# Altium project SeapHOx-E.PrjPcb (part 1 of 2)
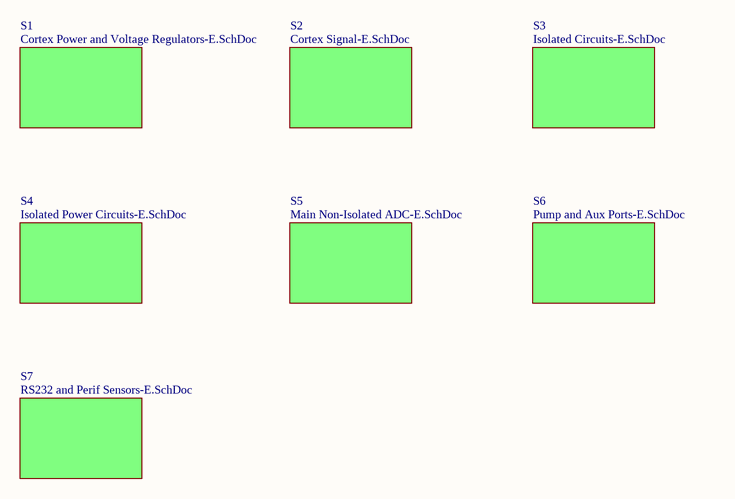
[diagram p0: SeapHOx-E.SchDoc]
8 sheets, 244 parts. Net scope: global (net labels, ports and power ports of the same name join across sheets).
Board file: SeapHOx-E.PcbDoc
Sheets:
  SeapHOx-E.SchDoc
    S1 = Cortex Power and Voltage Regulators-E.SchDoc
    S2 = Cortex Signal-E.SchDoc
    S3 = Isolated Circuits-E.SchDoc
    S7 = RS232 and Perif Sensors-E.SchDoc
    S4 = Isolated Power Circuits-E.SchDoc
    S5 = Main Non-Isolated ADC-E.SchDoc
    S6 = Pump and Aux Ports-E.SchDoc

## Sheet SeapHOx-E.SchDoc: SeapHOx ARM Controller
size Letter; PageSetup: Record=PageOptions¦CenterHorizontal=True¦CenterVertical=True¦PrintScale=0.94¦XCorrection=1.00¦YCorrection=1.00¦PrintKind=1¦BorderSize=5000000¦LeftOffset=0¦BottomOffset=0¦Orientation=2¦PaperLength=1000¦PaperWidth=1000¦Scale=100¦PaperSource=7¦PrintQuality=-4¦MediaType=1¦DitherType=10¦PaperKind=Letter¦PrintScaleMode=1

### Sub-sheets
S1 = Cortex Power and Voltage Regulators-E.SchDoc: no entries
S2 = Cortex Signal-E.SchDoc: no entries
S3 = Isolated Circuits-E.SchDoc: no entries
S4 = Isolated Power Circuits-E.SchDoc: no entries
S5 = Main Non-Isolated ADC-E.SchDoc: no entries
S6 = Pump and Aux Ports-E.SchDoc: no entries
S7 = RS232 and Perif Sensors-E.SchDoc: no entries

## Sheet Cortex Power and Voltage Regulators-E.SchDoc: SeapHOx ARM Controller
size Letter; DocumentNumber: 1; Revision: E; SheetNumber: 4; SheetTotal: 7; PageSetup: Record=PageOptions¦CenterHorizontal=True¦CenterVertical=True¦PrintScale=0.94¦XCorrection=1.00¦YCorrection=1.00¦PrintKind=0¦BorderSize=5000000¦LeftOffset=0¦BottomOffset=0¦Orientation=2¦PaperLength=1000¦PaperWidth=1000¦Scale=100¦PaperSource=7¦PrintQuality=-4¦MediaType=1¦DitherType=10¦PaperKind=Letter¦PrintScaleMode=1
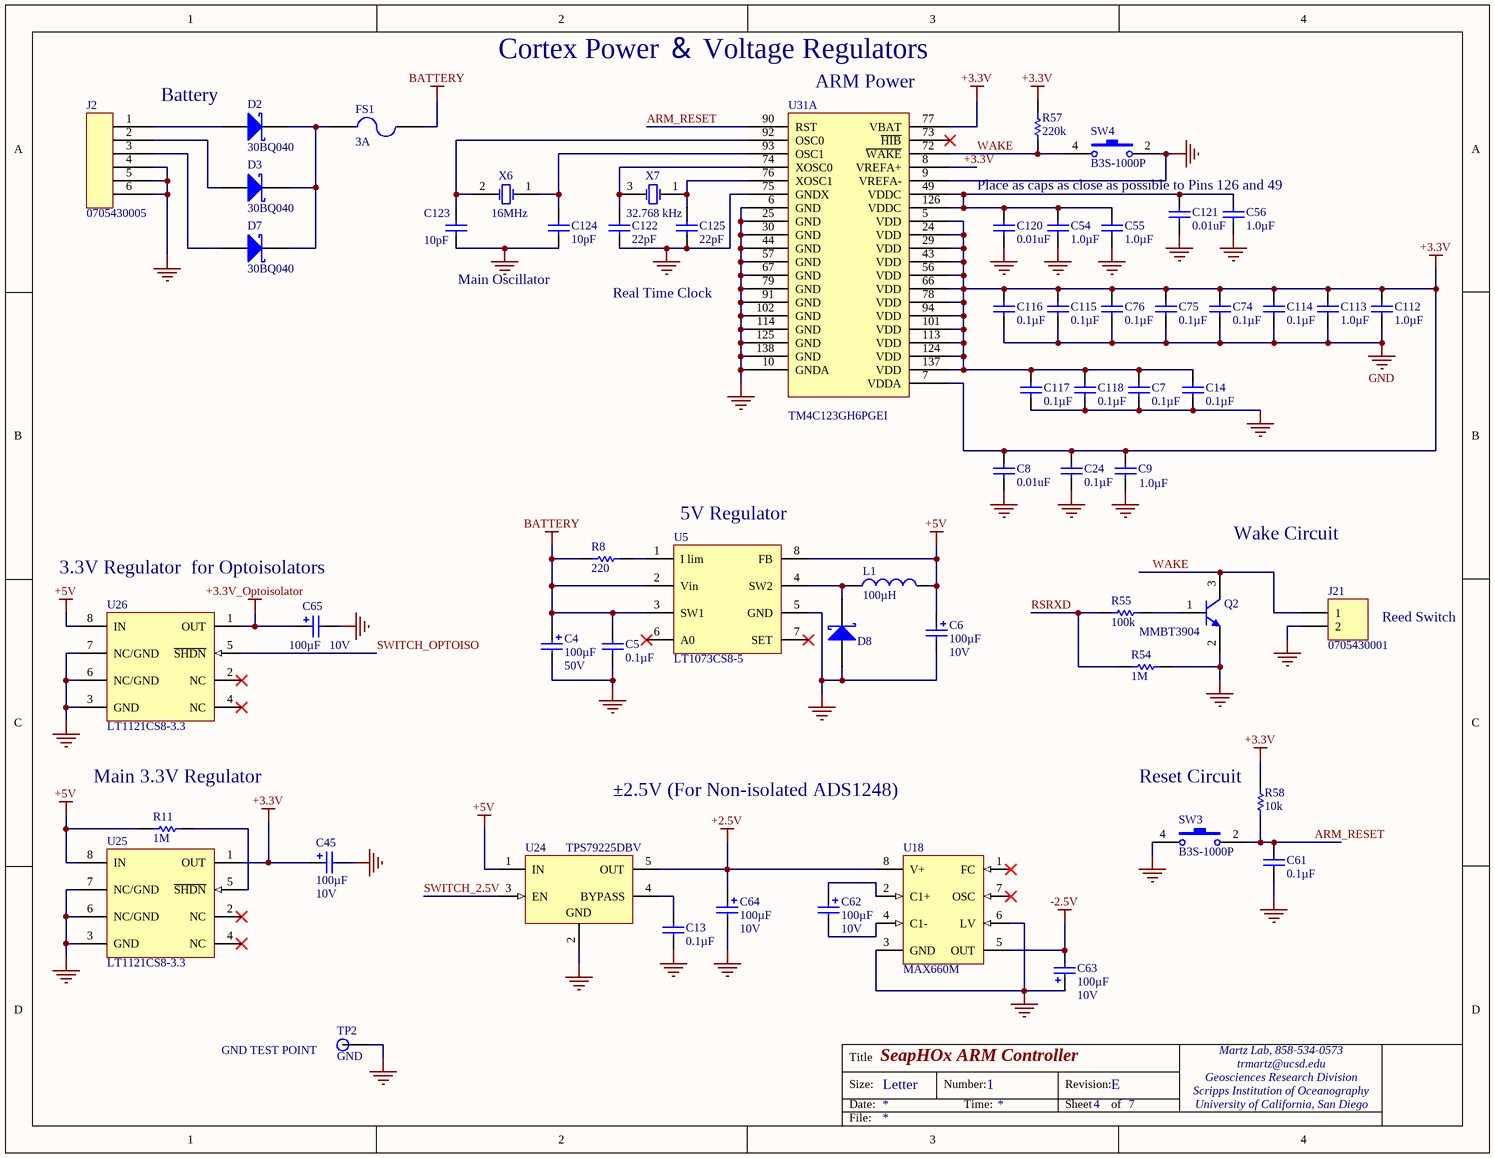
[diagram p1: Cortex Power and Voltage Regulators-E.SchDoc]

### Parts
C4  Capacitance: 100µF  Voltage Rating: 50V  [CAP-VS-HA]  (hidden comment: EEE-1HA101UP)
C5  Capacitance: 0.1µF  [CAPC0603(1608)100_M]  (hidden comment: 0.1uF/50V)
C6  Capacitance: 100µF  Voltage - Rated: 10V  [CAPMP7343X29N]  (hidden comment: T495D107K010ATE100)
C7  Capacitance: 0.1µF  [CAPC0603(1608)100_M]  (hidden comment: 0.1uF/50V)
C8  0.01uF  [CAPC0603(1608)100_M]
C9  Capacitance: 1.0µF  [CAPC0603(1608)100_M]
C13  Capacitance: 0.1µF  [CAPC0603(1608)100_M]  (hidden comment: 0.1uF/50V)
C14  Capacitance: 0.1µF  [CAPC0603(1608)100_M]  (hidden comment: 0.1uF/50V)
C24  Capacitance: 0.1µF  [CAPC0603(1608)100_M]  (hidden comment: 0.1uF/50V)
C45  Capacitance: 100µF  Voltage - Rated: 10V  [CAPMP7343X29N]  (hidden comment: T495D107K010ATE100)
C54  Capacitance: 1.0µF  [CAPC0603(1608)100_M]  (hidden comment: C1608X5R1H105K080AB)
C55  Capacitance: 1.0µF  [CAPC0603(1608)100_M]  (hidden comment: C1608X5R1H105K080AB)
C56  Capacitance: 1.0µF  [CAPC0603(1608)100_M]  (hidden comment: C1608X5R1H105K080AB)
C61  Capacitance: 0.1µF  [CAPC0603(1608)100_M]  (hidden comment: 0.1uF/50V)
C62  Capacitance: 100µF  Voltage - Rated: 10V  [CAPMP7343X29N]  (hidden comment: T495D107K010ATE100)
C63  Capacitance: 100µF  Voltage - Rated: 10V  [CAPMP7343X29N]  (hidden comment: T495D107K010ATE100)
C64  Capacitance: 100µF  Voltage - Rated: 10V  [CAPMP7343X29N]  (hidden comment: T495D107K010ATE100)
C65  Capacitance: 100µF  Voltage - Rated: 10V  [CAPMP7343X29N]  (hidden comment: T495D107K010ATE100)
C74  Capacitance: 0.1µF  [CAPC0603(1608)100_M]  (hidden comment: 0.1uF/50V)
C75  Capacitance: 0.1µF  [CAPC0603(1608)100_M]  (hidden comment: 0.1uF/50V)
C76  Capacitance: 0.1µF  [CAPC0603(1608)100_M]  (hidden comment: 0.1uF/50V)
C112  Capacitance: 1.0µF  [CAPC0603(1608)100_M]  (hidden comment: C1608X5R1H105K080AB)
C113  Capacitance: 1.0µF  [CAPC0603(1608)100_M]  (hidden comment: C1608X5R1H105K080AB)
C114  Capacitance: 0.1µF  [CAPC0603(1608)100_M]  (hidden comment: 0.1uF/50V)
C115  Capacitance: 0.1µF  [CAPC0603(1608)100_M]  (hidden comment: 0.1uF/50V)
C116  Capacitance: 0.1µF  [CAPC0603(1608)100_M]  (hidden comment: 0.1uF/50V)
C117  Capacitance: 0.1µF  [CAPC0603(1608)100_M]  (hidden comment: 0.1uF/50V)
C118  Capacitance: 0.1µF  [CAPC0603(1608)100_M]  (hidden comment: 0.1uF/50V)
C120  0.01uF  [CAPC0603(1608)100_M]
C121  0.01uF  [CAPC0603(1608)100_M]
C122  Capacitance: 22pF  [CAPC0603(1608)100_M]  (hidden comment: C1608C0G1H220J080AA)
C123  Capacitance: 10pF  [CAPC0603(1608)100_M]  (hidden comment: C1608C0G1H100D080AA)
C124  Capacitance: 10pF  [CAPC0603(1608)100_M]  (hidden comment: C1608C0G1H100D080AA)
C125  Capacitance: 22pF  [CAPC0603(1608)100_M]  (hidden comment: C1608C0G1H220J080AA)
D2  30BQ040  [DO-214AB]
D3  30BQ040  [DO-214AB]
D7  30BQ040  [DO-214AB]
D8  VS-10BQ100TRPBF  [DO-214AA]  (value not drawn)
FS1  Current Rating: 3A  [FUSE-NANO-SMD]  (hidden comment: 5A)
J2  0705430005  [70543-0005]
J21  0705430001  [70543-0001]
L1  Inductance: 100µH  [ELLATV]  (hidden comment: ELL-ATV101M)
Q2  MMBT3904  [SOT23-3]
R8  Resistance (Ohms): 220  [RESC0805(2012)_N]  (hidden comment: ERJ-6GEYJ221V)
R11  Resistance (Ohms): 1M  [RESC0805(2012)_N]  (hidden comment: ERJ-6GEYJ105V)
R54  Resistance (Ohms): 1M  [RESC0805(2012)_N]  (hidden comment: ERJ-6GEYJ105V)
R55  Resistance (Ohms): 100k  [RESC0805(2012)_N]  (hidden comment: ERJ-6GEYJ104V)
R57  Resistance (Ohms): 220k  [RESC0805(2012)_N]  (hidden comment: ERJ-6GEYJ224V)
R58  Resistance (Ohms): 10k  [RESC0805(2012)_N]  (hidden comment: ERJ-6GEYJ103V)
SW3  B3S-1000P  [B3S-100X]
SW4  B3S-1000P  [B3S-100X]
TP2  GND  [TEST-POINT-0.063]
U5  LT1073CS8-5  [SOIC8]
U18  MAX660M  [SOIC8]
U24  TPS79225DBV  [TI-DBV5]
U25  LT1121CS8-3.3  [SOIC8]
U26  LT1121CS8-3.3  [SOIC8]
U31  TM4C123GH6PGEI  [PGE144-M]  (part A of 3)
X6  Frequency: 16MHz  [ABM3]  (hidden comment: 16.000 MHz)
X7  32.768 kHz  [AB26TRB]

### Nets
+2.5V: C64.1 U18.8(V+) U24.5(OUT)
+3.3V: C7.1 C8.1 C9.1 C14.1 C24.1 C45.1 C74.2 C75.2 C76.2 C112.1 C113.1 C114.2 C115.1 C116.1 C117.1 C118.1 R57.1 R58.2 U25.1(OUT) U31.5(VDD) U31.7(VDDA) U31.8(VREFA+) U31.24(VDD) U31.29(VDD) U31.43(VDD) U31.56(VDD) U31.66(VDD) U31.77(VBAT) U31.78(VDD) U31.94(VDD) U31.101(VDD) U31.113(VDD) U31.124(VDD) U31.137(VDD)
+3.3V_Optoisolator: C65.1 U26.1(OUT)
+5V: C6.1 L1.2 R11.2 U5.8(FB) U24.1(IN) U25.8(IN) U26.8(IN)
-2.5V: C63.2 U18.5(OUT)
BATTERY: C4.1 C5.2 FS1.2 R8.1 U5.2(Vin) U5.3(SW1)
GND: C4.2 C5.1 C6.2 C7.2 C8.2 C9.2 C13.1 C14.2 C24.2 C45.2 C54.2 C55.2 C56.2 C61.1 C63.1 C64.2 C65.2 C74.1 C75.1 C76.1 C112.2 C113.2 C114.1 C115.2 C116.2 C117.2 C118.2 C120.2 C121.2 C122.2 C123.2 C124.2 C125.2 D8.1(A) J2.4 J2.5 J2.6 J21.2 Q2.2(E) R54.1 SW3.4 SW4.2 TP2.1(TP) U5.5(GND) U18.3(GND) U18.6(LV) U24.2(GND) U25.3(GND) U25.6(NC/GND) U25.7(NC/GND) U26.3(GND) U26.6(NC/GND) U26.7(NC/GND) U31.6(GND) U31.9(VREFA-) U31.10(GNDA) U31.25(GND) U31.30(GND) U31.44(GND) U31.57(GND) U31.67(GND) U31.75(GNDX) U31.79(GND) U31.91(GND) U31.102(GND) U31.114(GND) U31.125(GND) U31.138(GND)
ARM_RESET: C61.2 R58.1 SW3.2 U31.90(RST)
RSRXD: R54.2 R55.2
SWITCH_2.5V: U24.3(EN)
SWITCH_OPTOISO: U26.5(~{SHDN})
WAKE: J21.1 Q2.3(C) R57.2 SW4.4 U31.72(~{WAKE})
NetC13_2: C13.2 U24.4(BYPASS)
NetC54_1: C54.1 C55.1 C56.1 C120.1 C121.1 U31.49(VDDC) U31.126(VDDC)
NetC62_1: C62.1 U18.2(C1+)
NetC62_2: C62.2 U18.4(C1-)
NetC122_1: C122.1 U31.74(XOSC0) X7.3(OSC1)
NetC123_1: C123.1 U31.92(OSC0) X6.2(OSC1)
NetC124_1: C124.1 U31.93(OSC1) X6.1(OSC2)
NetC125_1: C125.1 U31.76(XOSC1) X7.1(OSC2)
NetD2_1: D2.1(A) J2.1
NetD2_2: D2.2(K) D3.2(K) D7.2(K) FS1.1
NetD3_1: D3.1(A) J2.2
NetD7_1: D7.1(A) J2.3
NetD8_2: D8.2(K) L1.1 U5.4(SW2)
NetQ2_1: Q2.1(B) R55.1
NetR8_2: R8.2 U5.1(I_lim)
NetR11_1: R11.1 U25.5(~{SHDN})

Not connected (* = marked no-connect by the designer): U5 6(A0)* 7(SET)*; U18 1(FC)* 7(OSC)*; U25 2(NC)* 4(NC)*; U26 2(NC)* 4(NC)*; U31 73(~{HIB})*

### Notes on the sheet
- (near D2) Battery
- Cortex Power ＆ Voltage Regulators
- (near U31) ARM Power
- Place as caps as close as possible to Pins 126 and 49
- Main Oscillator
- Real Time Clock
- (near U5) 5V Regulator
- Wake Circuit
- 3.3V Regulator  for Optoisolators
- Reed Switch
- Main 3.3V Regulator
- ±2.5V (For Non-isolated ADS1248)
- (near R58) Reset Circuit
- (near TP2) GND TEST POINT

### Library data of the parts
C4 = EEE-1HA101UP: CAP ALUM 100UF 50V 20% SMD; Manufacturer: Panasonic Electronic Components; Lifetime @ Temp.: 2000 Hrs @ 85°C; Ripple Current: 200mA; Surface Mount Land Size: 0.327" L x 0.327" W (8.30mm x 8.30mm)
C5 C7 C13 C14 C24 C61 C74-C76 C114-C118 = C0603C104K5RACTU: CAP CER 0.1UF 50V 10% X7R 0603; Manufacturer: Kemet
C6 C45 C62-C65 = T495D107K010ATE100: CAP TANT 100UF 10V 10% 2917; Manufacturer: Kemet; Manufacturer Size Code: D; ESR (Equivalent Series Resistance): 100 mOhm; Type: Molded; Lifetime @ Temp.: 2000 Hrs @ 85°C
C8 C120 C121 = C1608X7R1H103K080AA: CAP CER 10000PF 50V 10% X7R 0603; Manufacturer: TDK Corporation
C9 C54-C56 C112 C113 = C1608X5R1H105K080AB: CAP CER 1UF 50V 10% X5R 0603; Manufacturer: TDK Corporation
C122 C125 = C1608C0G1H220J080AA: CAP CER 22PF 50V 5% NP0 0603; Manufacturer: TDK Corporation; Temperature Coefficient: C0G, NP0
C123 C124 = C1608C0G1H100D080AA: CAP CER 10PF 50V NP0 0603; Manufacturer: TDK Corporation; Tolerance: ±0.5pF; Temperature Coefficient: C0G, NP0
D2 D3 D7 = VS-30BQ040TRPBF: DIODE SCHOTTKY 40V 3A SMC; Manufacturer: Vishay Semiconductor Diodes Division; Voltage - Forward (Vf) (Max) @ If: 530mV @ 3A; Speed: Fast Recovery =< 500ns, > 200mA (Io); Current - Reverse Leakage @ Vr: 500µA @ 40V; Thermal Resistance: 12°C/W Jl
D8 = VS-10BQ100TRPBF: DIODE SCHOTTKY 100V 1A DO214AA; Manufacturer: Vishay Semiconductor Diodes Division; Voltage - Forward (Vf) (Max) @ If: 780mV @ 1A; Speed: Fast Recovery =< 500ns, > 200mA (Io); Current - Reverse Leakage @ Vr: 500µA @ 100V; Thermal Resistance: 36°C/W Jl
FS1 = 0157003.DR: FUSE FAST 125VAC, 125VDC 3A SMD; Manufacturer: Littelfuse Inc; Fuse Type: Board Mount (Cartridge Style Excluded); Voltage Rating - AC: 125V; Breaking Capacity @ Rated Voltage: 50A; Melting I²t: 1.65; Approvals: cULus, PSE; DC Cold Resistance: 0.0229 Ohm
J2 = 0705430005: CONN HEADER 6POS .100 VERT GOLD; Manufacturer: Molex Inc; Connector Type: Header, Shrouded; Number of Positions: 6; Number of Positions Loaded: All; Pitch: 0.100" (2.54mm)
J21 = 0705430001: CONN HEADER 2POS .100 VERT GOLD; Manufacturer: Molex Inc; Connector Type: Header, Shrouded; Number of Positions: 2; Number of Positions Loaded: All; Pitch: 0.100" (2.54mm)
L1 = ELL-ATV101M: COIL PWR CHOKE 100UH 1A SMD; Manufacturer: Panasonic Electronic Components; Type: Wirewound; Material - Core: Ferrite; Tolerance: ±20%; Shielding: Shielded; DC Resistance (DCR): 180 mOhm; Frequency - Test: 100kHz
Q2 = MMBT3904: TRANSISTOR NPN GP 40V SOT23; Manufacturer: Micro Commercial Co; Manufacturer Part Number: MMBT3904-TP; Current - Collector (Ic) (Max): 200mA; Vce Saturation (Max) @ Ib, Ic: 300mV @ 5mA, 50mA; DC Current Gain (hFE) (Min) @ Ic, Vce: 100 @ 10mA, 1V; Power - Max: 350mW; Frequency - Transition: 300MHz
R8 = ERJ-6GEYJ221V: RES 220 OHM 1/8W 5% 0805 SMD; Manufacturer: Panasonic Electronic Components; Power (Watts): 0.125W, 1/8W; Temperature Coefficient: ±200ppm/°C
R11 R54 = ERJ-6GEYJ105V: RES 1M OHM 1/8W 5% 0805 SMD; Manufacturer: Panasonic Electronic Components; Power (Watts): 0.125W, 1/8W; Temperature Coefficient: ±200ppm/°C
R55 = ERJ-6GEYJ104V: RES 100K OHM 1/8W 5% 0805 SMD; Manufacturer: Panasonic Electronic Components; Power (Watts): 0.125W, 1/8W; Temperature Coefficient: ±200ppm/°C
R57 = ERJ-6GEYJ224V: RES 220K OHM 1/8W 5% 0805 SMD; Manufacturer: Panasonic Electronic Components; Power (Watts): 0.125W, 1/8W; Temperature Coefficient: ±200ppm/°C
R58 = ERJ-6GEYJ103V: RES 10K OHM 1/8W 5% 0805 SMD; Manufacturer: Panasonic Electronic Components; Power (Watts): 0.125W, 1/8W; Temperature Coefficient: ±200ppm/°C
SW3 SW4 = B3S-1000P: SWITCH TACTILE SPST-NO 0.05A 24V; Manufacturer: Omron Electronics Inc-EMC Div; Switch Function: Off-Mom; Contact Rating @ Voltage: 0.05A @ 24VDC; Actuator Type: Standard; Actuator Height off PCB, from Pins: 4.30mm; Actuator Orientation: Top Actuated; Outline: 6.60mm x 6.00mm; Illumination: Non-Illuminated; Operating Force: 160gf; Ingress Protection: IP67 - Dust Tight, Waterproof; Switch Travel: 0.25mm; Mechanical Life: 500,000 Cycles
TP2 = 5006: TEST POINT PC COMPACT .063"D BLK; Manufacturer: Keystone Electronics
U5 = LT1073CS8-5: IC REG BUCK BST INV 5V .4A 8SOIC; Manufacturer: Linear Technology; Manufacturer Part Number: LT1073CS8-5#PBF; Output Type: Fixed; Number of Outputs: 1; Voltage - Input: 1 V ~ 30 V; Frequency - Switching: 19kHz; Current - Output: 400mA; Synchronous Rectifier: No
U18 = MAX660M: IC REG MULTI CONFIG ADJ 8-SOIC; Manufacturer: Texas Instruments; Manufacturer Part Number: MAX660MX/NOPB; Output Type: Adjustable; Number of Outputs: 1; Voltage - Input: 1.5 V ~ 5.5 V; Frequency - Switching: 10kHz, 80kHz; Current - Output: 100mA; Synchronous Rectifier: No
U24 = TPS79225DBVT: IC REG LDO 2.5V 0.1A SOT23-5; Manufacturer: Texas Instruments; Number of Regulators: 1; Regulator Topology: Positive Fixed; Voltage - Input: 2.7 V ~ 5.5 V; Current - Output: 100mA (Max); Current - Limit (Min): 285mA
U25 U26 = LT1121CS8-3.3: IC REG LDO 3.3V 0.15A 8SOIC; Manufacturer: Linear Technology; Manufacturer Part Number: LT1121CS8-3.3#PBF; Number of Regulators: 1; Regulator Topology: Positive Fixed; Voltage - Input: 4.17 V ~ 30 V; Voltage - Dropout (Typical): 0.42V @ 150mA; Current - Output: 150mA
U31 = TM4C123GH6PGEI: IC MCU 32BIT 256KB FLASH 144LQFP; Manufacturer: Texas Instruments; Core Processor: ARM® Cortex™-M4F; Core Size: 32-Bit; Speed: 80MHz; Connectivity: CAN, I²C, IrDA, Microwire, QEI, SPI, SSI, UART/USART, USB OTG; Peripherals: Brown-out Detect/Reset, DMA, Motion PWM, POR, WDT; Number of I /O: 105; Program Memory Size: 256KB (256K x 8); EEPROM Size: 2K x 8; RAM Size: 32K x 8; Voltage - Supply (Vcc/Vdd): 1.08 V ~ 3.63 V; Data Converters: A/D 24x12b; Oscillator Type: Internal
X6 = ABM3-16.000MHZ-D2Y-T: CRYSTAL 16MHZ 18PF SMD; Manufacturer: Abracon Corporation; Frequency Stability: ±30ppm; Frequency Tolerance: ±20ppm; ESR (Equivalent Series Resistance): 40 Ohm; Operating Mode: Fundamental
X7 = AB26TRB-32.768KHZ-T: CRYSTAL 32.768KHZ 12.5PF THRU; Manufacturer: Abracon Corporation; Frequency Tolerance: ±20ppm; ESR (Equivalent Series Resistance): 50 kOhm; Operating Mode: Fundamental

## Sheet Cortex Signal-E.SchDoc: SeapHOx ARM Controller
size Letter; DocumentNumber: 1; Revision: E; SheetNumber: 3; SheetTotal: 7; PageSetup: Record=PageOptions¦CenterHorizontal=True¦CenterVertical=True¦PrintScale=0.94¦XCorrection=1.00¦YCorrection=1.00¦PrintKind=0¦BorderSize=5000000¦LeftOffset=0¦BottomOffset=0¦Orientation=2¦PaperLength=1000¦PaperWidth=1000¦Scale=100¦PaperSource=273¦PrintQuality=600¦MediaType=1¦DitherType=10¦PrintScaleMode=1¦PaperKind=Letter¦PaperIndex=1
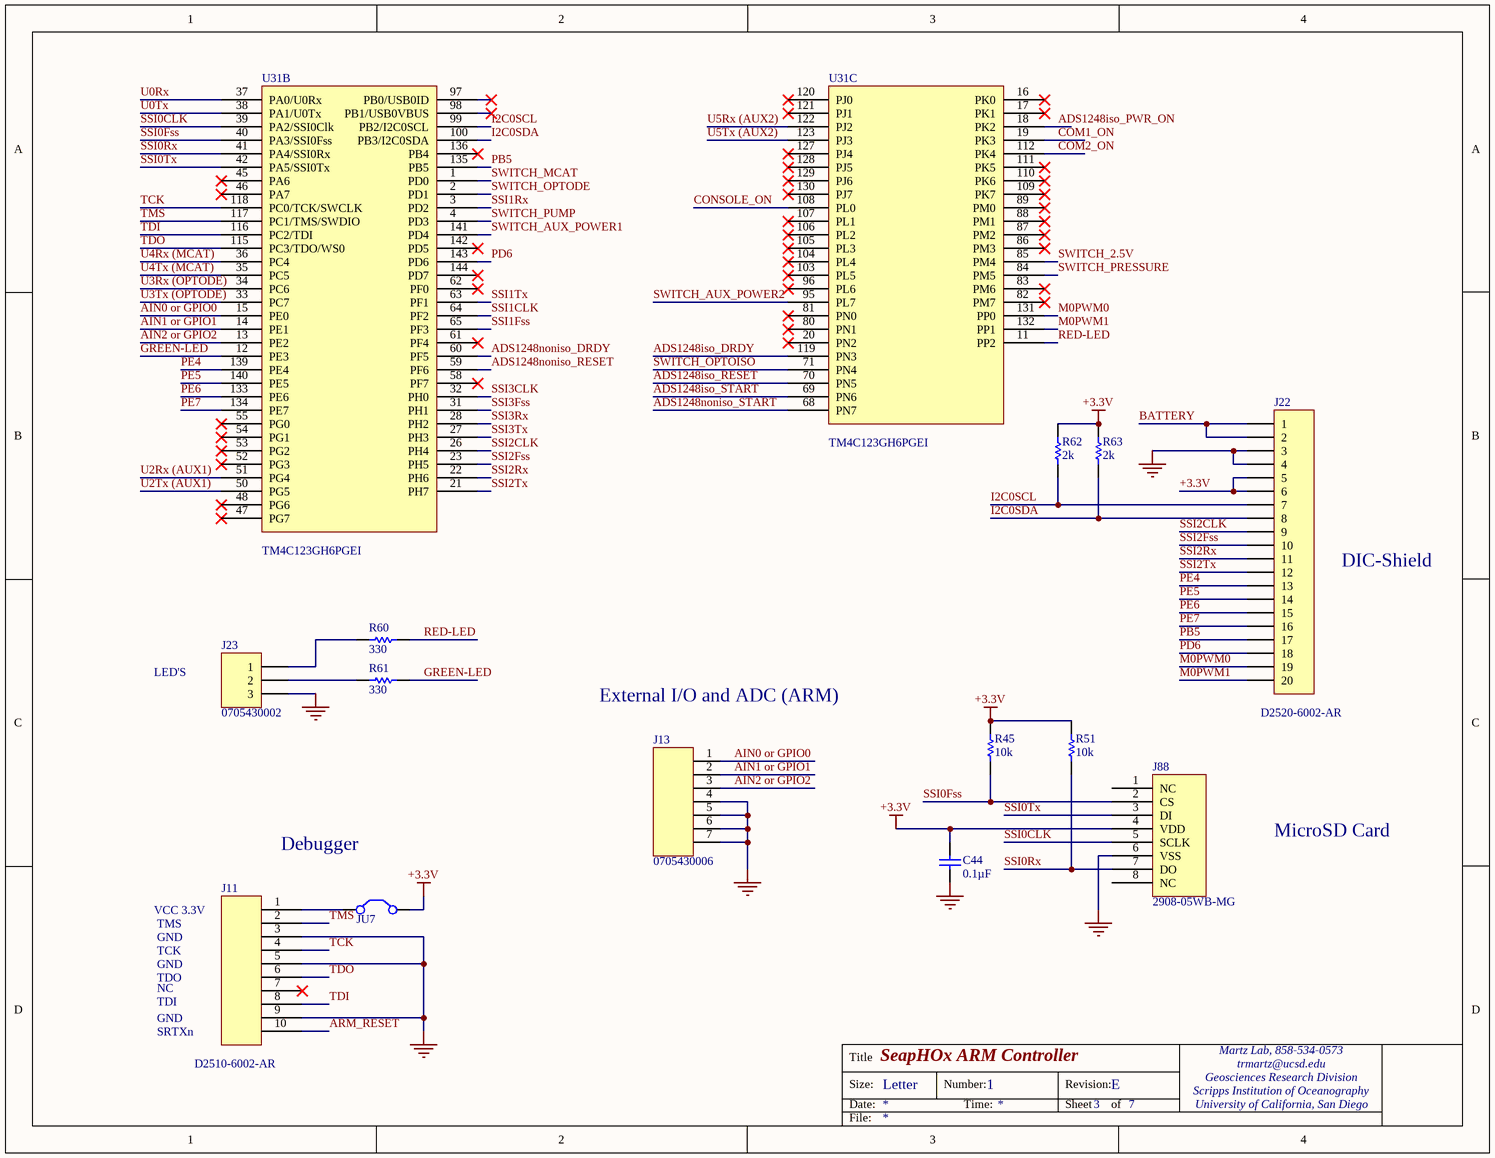
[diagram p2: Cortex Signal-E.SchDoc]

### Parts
C44  Capacitance: 0.1µF  [CAPC0603(1608)100_M]  (hidden comment: 0.1uF/50V)
J11  D2510-6002-AR  [D2510-6002]
J13  0705430006  [70543-0006]
J22  D2520-6002-AR  [D2520-6002]
J23  0705430002  [70543-0002]
J88  2908-05WB-MG  [2908-05]
JU7  68001-202HLF  [Jump-2 100mil]  (value not drawn)
R45  Resistance (Ohms): 10k  [RESC0805(2012)_N]  (hidden comment: ERJ-6GEYJ103V)
R51  Resistance (Ohms): 10k  [RESC0805(2012)_N]  (hidden comment: ERJ-6GEYJ103V)
R60  Resistance (Ohms): 330  [RESC0805(2012)_N]  (hidden comment: ERJ-6GEYJ331V)
R61  Resistance (Ohms): 330  [RESC0805(2012)_N]  (hidden comment: ERJ-6GEYJ331V)
R62  Resistance (Ohms): 2k  [RESC0805(2012)_N]  (hidden comment: ERJ-6GEYJ202V)
R63  Resistance (Ohms): 2k  [RESC0805(2012)_N]  (hidden comment: ERJ-6GEYJ202V)
U31  TM4C123GH6PGEI  [PGE144-M]  (parts B,C of 3)

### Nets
+3.3V: C44.2 J22.5 J22.6 J88.4(VDD) JU7.2(C2) R45.2 R51.2 R62.2 R63.2
BATTERY: J22.1 J22.2
GND: C44.1 J11.3 J11.5 J11.9 J13.4 J13.5 J13.6 J13.7 J22.3 J22.4 J23.3 J88.6(VSS)
ADS1248iso_DRDY: U31.119(PN3)
ADS1248iso_PWR_ON: U31.18(PK2)
ADS1248iso_RESET: U31.70(PN5)
ADS1248iso_START: U31.69(PN6)
ADS1248noniso_DRDY: U31.60(PF5)
ADS1248noniso_RESET: U31.59(PF6)
ADS1248noniso_START: U31.68(PN7)
AIN0 or GPIO0: J13.1 U31.15(PE0)
AIN1 or GPIO1: J13.2 U31.14(PE1)
AIN2 or GPIO2: J13.3 U31.13(PE2)
ARM_RESET: J11.10
COM1_ON: U31.19(PK3)
COM2_ON: U31.112(PK4)
CONSOLE_ON: U31.108(PL0)
GREEN-LED: R61.2 U31.12(PE3)
I2C0SCL: J22.7 R62.1 U31.99(PB2/I2C0SCL)
I2C0SDA: J22.8 R63.1 U31.100(PB3/I2C0SDA)
M0PWM0: J22.19 U31.131(PP0)
M0PWM1: J22.20 U31.132(PP1)
PB5: J22.17 U31.135(PB5)
PD6: J22.18 U31.143(PD6)
PE4: J22.13 U31.139(PE4)
PE5: J22.14 U31.140(PE5)
PE6: J22.15 U31.133(PE6)
PE7: J22.16 U31.134(PE7)
RED-LED: R60.2 U31.11(PP2)
SSI0CLK: J88.5(SCLK) U31.39(PA2/SSI0Clk)
SSI0Fss: J88.2(CS) R45.1 U31.40(PA3/SSI0Fss)
SSI0Rx: J88.7(DO) R51.1 U31.41(PA4/SSI0Rx)
SSI0Tx: J88.3(DI) U31.42(PA5/SSI0Tx)
SSI1CLK: U31.64(PF2)
SSI1Fss: U31.65(PF3)
SSI1Rx: U31.3(PD2)
SSI1Tx: U31.63(PF1)
SSI2CLK: J22.9 U31.26(PH4)
SSI2Fss: J22.10 U31.23(PH5)
SSI2Rx: J22.11 U31.22(PH6)
SSI2Tx: J22.12 U31.21(PH7)
SSI3CLK: U31.32(PH0)
SSI3Fss: U31.31(PH1)
SSI3Rx: U31.28(PH2)
SSI3Tx: U31.27(PH3)
SWITCH_2.5V: U31.85(PM4)
SWITCH_AUX_POWER1: U31.141(PD4)
SWITCH_AUX_POWER2: U31.95(PL7)
SWITCH_MCAT: U31.1(PD0)
SWITCH_OPTODE: U31.2(PD1)
SWITCH_OPTOISO: U31.71(PN4)
SWITCH_PRESSURE: U31.84(PM5)
SWITCH_PUMP: U31.4(PD3)
TCK: J11.4 U31.118(PC0/TCK/SWCLK)
TDI: J11.8 U31.116(PC2/TDI)
TDO: J11.6 U31.115(PC3/TDO/WS0)
TMS: J11.2 U31.117(PC1/TMS/SWDIO)
U0Rx: U31.37(PA0/U0Rx)
U0Tx: U31.38(PA1/U0Tx)
U2Rx (AUX1): U31.51(PG4)
U2Tx (AUX1): U31.50(PG5)
U3Rx (OPTODE): U31.34(PC6)
U3Tx (OPTODE): U31.33(PC7)
U4Rx (MCAT): U31.36(PC4)
U4Tx (MCAT): U31.35(PC5)
U5Rx (AUX2): U31.122(PJ2)
U5Tx (AUX2): U31.123(PJ3)
NetJ11_1: J11.1 JU7.1(C1)
NetJ23_1: J23.1 R60.1
NetJ23_2: J23.2 R61.1

Not connected (* = marked no-connect by the designer): J11 7*; J88 1(NC) 8(NC); U31 16(PK0)* 17(PK1)* 20(PN2)* 45(PA6)* 46(PA7)* 47(PG7)* 48(PG6)* 52(PG3)* 53(PG2)* 54(PG1)* 55(PG0)* 58(PF7)* 61(PF4)* 62(PF0)* 80(PN1)* 81(PN0)* 82(PM7)* 83(PM6)* 86(PM3)* 87(PM2)* 88(PM1)* 89(PM0)* 96(PL6)* 97(PB0/USB0ID)* 98(PB1/USB0VBUS)* 103(PL5)* 104(PL4)* 105(PL3)* 106(PL2)* 107(PL1)* 109(PK7)* 110(PK6)* 111(PK5)* 120(PJ0)* 121(PJ1)* 127(PJ4)* 128(PJ5)* 129(PJ6)* 130(PJ7)* 136(PB4)* 142(PD5)* 144(PD7)*

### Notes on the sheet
- DIC-Shield
- LED'S
- External I/O and ADC (ARM)
- MicroSD Card
- Debugger
- VCC 3.3V
- TMS
- GND
- TCK
- TDO
- NC
- TDI
- SRTXn

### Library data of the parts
C44 = C0603C104K5RACTU: as C5 on sheet Cortex Power and Voltage Regulators-E
J11 = D2510-6002-AR: CONN HEADER 10POS VERT 10GOLD; Manufacturer: 3M; Connector Type: Header, Shrouded; Number of Positions: 10; Number of Positions Loaded: All; Pitch: 0.100" (2.54mm)
J13 = 0705430006: CONN HEADER 7POS .100 VERT GOLD; Manufacturer: Molex Inc; Connector Type: Header, Shrouded; Number of Positions: 7; Number of Positions Loaded: All; Pitch: 0.100" (2.54mm)
J22 = D2520-6002-AR: CONN HEADER 20POS VERT 10GOLD; Manufacturer: 3M; Connector Type: Header, Shrouded; Number of Positions: 20; Number of Positions Loaded: All; Pitch: 0.100" (2.54mm)
J23 = 0705430002: CONN HEADER 3POS .100 VERT GOLD; Manufacturer: Molex Inc; Connector Type: Header, Shrouded; Number of Positions: 3; Number of Positions Loaded: All; Pitch: 0.100" (2.54mm)
J88 = 2908-05WB-MG: CONN EJECT MICROSD PUSH-PUSH SMD; Manufacturer: 3M; Card Type: Secure Digital - microSD™; Number of Positions: 10 (8 + 2); Connector Type: Connector and Ejector; Insertion, Removal Method: Push In, Push Out
JU7 = 68001-202HLF: BERGSTIK II .100" SR STRAIGHT; Manufacturer: FCI; Connector Type: Header, Unshrouded; Number of Positions: 2; Number of Positions Loaded: All; Pitch: 0.100" (2.54mm)
R45 R51 = ERJ-6GEYJ103V: as R58 on sheet Cortex Power and Voltage Regulators-E
R60 R61 = ERJ-6GEYJ331V: RES 330 OHM 1/8W 5% 0805 SMD; Manufacturer: Panasonic Electronic Components; Power (Watts): 0.125W, 1/8W; Temperature Coefficient: ±200ppm/°C
R62 R63 = ERJ-6GEYJ202V: RES 2K OHM 1/8W 5% 0805 SMD; Manufacturer: Panasonic Electronic Components; Power (Watts): 0.125W, 1/8W; Temperature Coefficient: ±200ppm/°C
U31 = TM4C123GH6PGEI: as U31 on sheet Cortex Power and Voltage Regulators-E

## Sheet Isolated Circuits-E.SchDoc: SeapHOx ARM Controller
size Letter; Organization: Martz Lab, 858-534-0573; Address1: trmartz@ucsd.edu; Address2: Geosciences Research; Address3: Division, Scripps Institution; Address4: of Oceanography, UCSD; DocumentNumber: 1; Revision: E; SheetNumber: 1; SheetTotal: 7
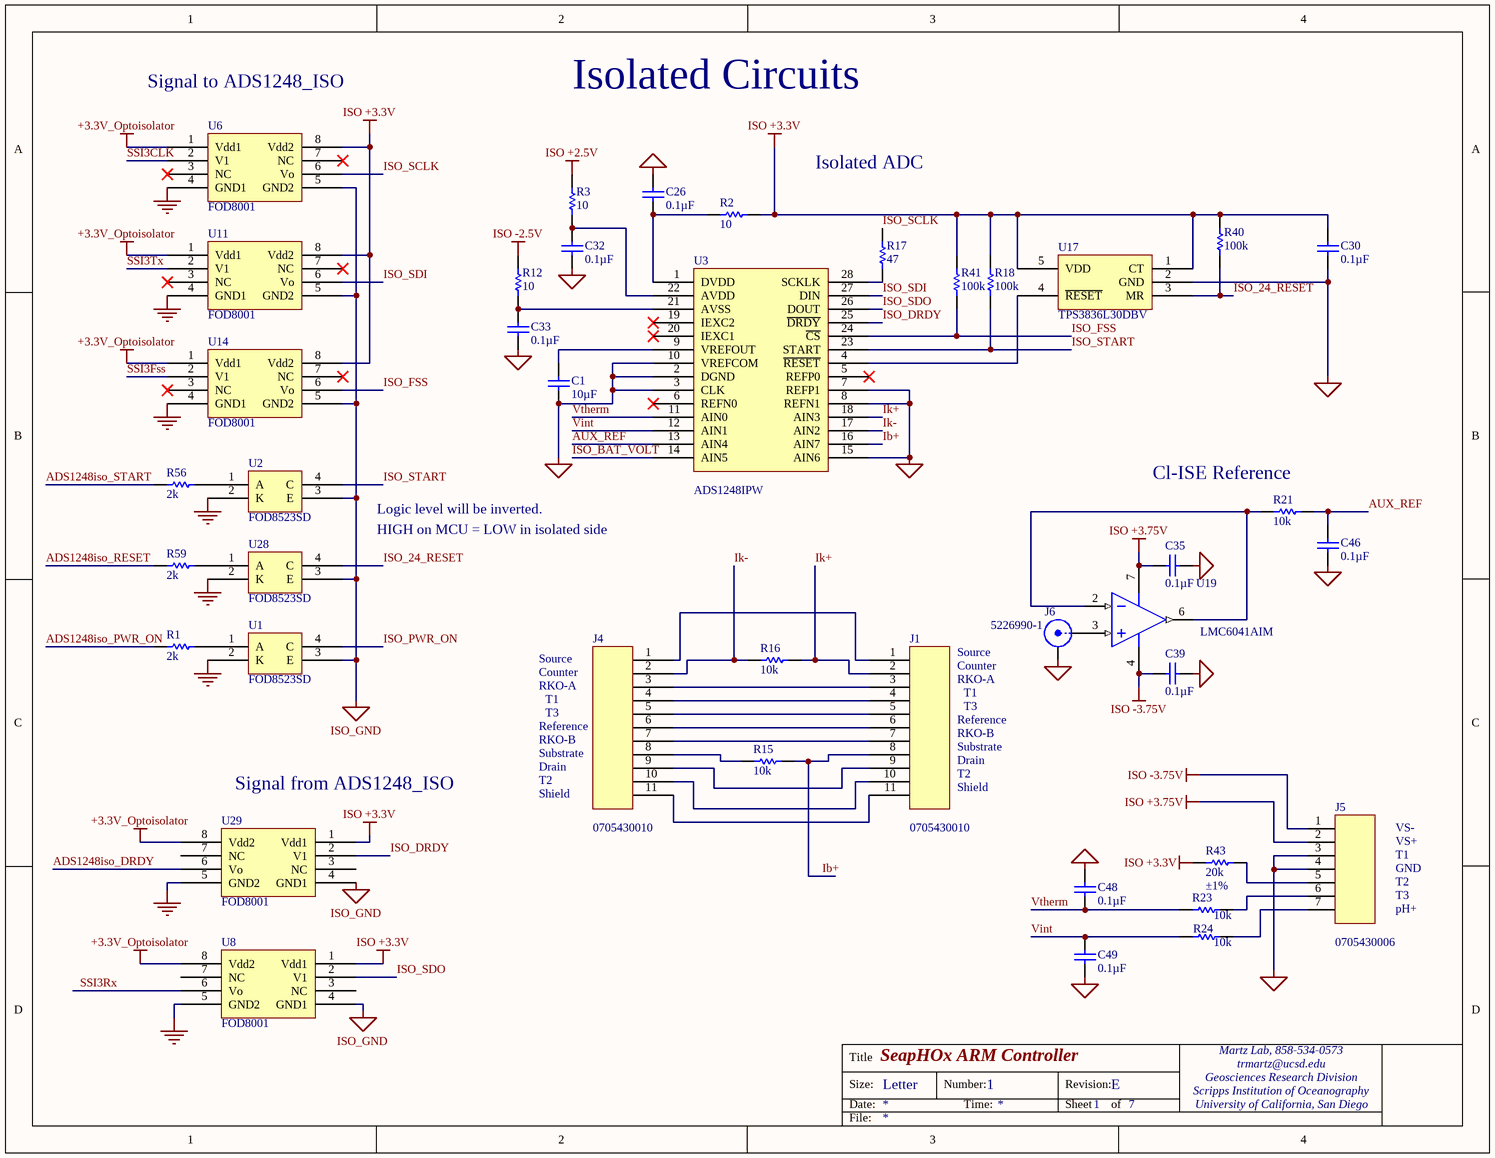
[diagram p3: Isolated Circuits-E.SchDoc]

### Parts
C1  Capacitance: 10µF  [CAPC0603(1608)100_M]  (hidden comment: C1608X5R1A106K080AC)
C26  Capacitance: 0.1µF  [CAPC0603(1608)100_M]  (hidden comment: 0.1uF/50V)
C30  Capacitance: 0.1µF  [CAPC0603(1608)100_M]  (hidden comment: 0.1uF/50V)
C32  Capacitance: 0.1µF  [CAPC0603(1608)100_M]  (hidden comment: 0.1uF/50V)
C33  Capacitance: 0.1µF  [CAPC0603(1608)100_M]  (hidden comment: 0.1uF/50V)
C35  Capacitance: 0.1µF  [CAPC0603(1608)100_M]  (hidden comment: 0.1uF/50V)
C39  Capacitance: 0.1µF  [CAPC0603(1608)100_M]  (hidden comment: 0.1uF/50V)
C46  Capacitance: 0.1µF  [CAPC0603(1608)100_M]  (hidden comment: 0.1uF/50V)
C48  Capacitance: 0.1µF  [CAPC0603(1608)100_M]  (hidden comment: 0.1uF/50V)
C49  Capacitance: 0.1µF  [CAPC0603(1608)100_M]  (hidden comment: 0.1uF/50V)
J1  0705430010  [70543-0010]
J4  0705430010  [70543-0010]
J5  0705430006  [70543-0006]
J6  5226990-1  [5226990-1]
R1  Resistance (Ohms): 2k  [RESC0805(2012)_N]  (hidden comment: ERJ-6GEYJ202V)
R2  Resistance (Ohms): 10  [RESC0805(2012)_N]  (hidden comment: ERJ-6GEYJ100V)
R3  Resistance (Ohms): 10  [RESC0805(2012)_N]  (hidden comment: ERJ-6GEYJ100V)
R12  Resistance (Ohms): 10  [RESC0805(2012)_N]  (hidden comment: ERJ-6GEYJ100V)
R15  Resistance (Ohms): 10k  [RESC0805(2012)_N]  (hidden comment: ERJ-6GEYJ103V)
R16  Resistance (Ohms): 10k  [RESC0805(2012)_N]  (hidden comment: ERJ-6GEYJ103V)
R17  Resistance (Ohms): 47  [RESC0603(1608)_N]  (hidden comment: ERJ-3GEYJ470V)
R18  Resistance (Ohms): 100k  [RESC0805(2012)_N]  (hidden comment: ERJ-6GEYJ104V)
R21  Resistance (Ohms): 10k  [RESC0805(2012)_N]  (hidden comment: ERJ-6GEYJ103V)
R23  Resistance (Ohms): 10k  [RESC0805(2012)_N]  (hidden comment: ERJ-6GEYJ103V)
R24  Resistance (Ohms): 10k  [RESC0805(2012)_N]  (hidden comment: ERJ-6GEYJ103V)
R40  Resistance (Ohms): 100k  [RESC0805(2012)_N]  (hidden comment: ERJ-6GEYJ104V)
R41  Resistance (Ohms): 100k  [RESC0805(2012)_N]  (hidden comment: ERJ-6GEYJ104V)
R43  Resistance (Ohms): 20k  Tolerance: ±1%  [RESC0805(2012)_N]  (hidden comment: ERJ-6ENF2002V)
R56  Resistance (Ohms): 2k  [RESC0805(2012)_N]  (hidden comment: ERJ-6GEYJ202V)
R59  Resistance (Ohms): 2k  [RESC0805(2012)_N]  (hidden comment: ERJ-6GEYJ202V)
U1  FOD8523SD  [4-SMD]
U2  FOD8523SD  [4-SMD]
U3  ADS1248  [TSSOP28]  (value not drawn)
U6  FOD8001  [MS-012-AA]
U8  FOD8001  [MS-012-AA]
U11  FOD8001  [MS-012-AA]
U14  FOD8001  [MS-012-AA]
U17  TPS3836L30DBV  [SOT23-5]
U19  LMC6041AIM  [MS-012-AA]
U28  FOD8523SD  [4-SMD]
U29  FOD8001  [MS-012-AA]

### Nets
+3.3V_Optoisolator: U6.1(Vdd1) U8.8(Vdd2) U11.1(Vdd1) U14.1(Vdd1) U29.8(Vdd2)
GND: U1.2(K) U2.2(K) U6.4(GND1) U8.5(GND2) U11.4(GND1) U14.4(GND1) U28.2(K) U29.5(GND2)
ISO +2.5V: R3.2
ISO +3.3V: C30.2 R2.2 R18.2 R40.2 R41.2 R43.1 U6.8(Vdd2) U8.1(Vdd1) U11.8(Vdd2) U14.8(Vdd2) U17.1(CT) U17.5(VDD) U29.1(Vdd1)
ISO +3.75V: C35.2 J5.2 U19.7(V+)
ISO -2.5V: R12.2
ISO -3.75V: C39.2 J5.1 U19.4(V-)
ISO_GND: C1.1 C26.2 C30.1 C32.1 C33.1 C35.1 C39.1 C46.1 C48.2 C49.1 J5.3 J5.4 J6.2(Y) U1.3(E) U2.3(E) U3.2(DGND) U3.3(CLK) U3.7(REFP1) U3.8(REFN1) U3.10(VREFCOM) U3.15(AIN6) U6.5(GND2) U8.4(GND1) U11.5(GND2) U14.5(GND2) U17.2(GND) U28.3(E) U29.4(GND1)
ADS1248iso_DRDY: U29.6(Vo)
ADS1248iso_PWR_ON: R1.1
ADS1248iso_RESET: R59.1
ADS1248iso_START: R56.1
AUX_REF: C46.2 R21.2 U3.13(AIN4)
Ib+: J1.8 R15.2 U3.16(AIN7)
Ik+: J1.2 R16.2 U3.18(AIN3)
Ik-: J4.2 R16.1 U3.17(AIN2)
ISO_24_RESET: R40.1 U17.3(MR) U28.4(C)
ISO_BAT_VOLT: U3.14(AIN5)
ISO_DRDY: U3.25(~{DRDY}) U29.2(V1)
ISO_FSS: R41.1 U3.24(~{CS}) U14.6(Vo)
ISO_PWR_ON: U1.4(C)
ISO_SCLK: R17.1 U6.6(Vo)
ISO_SDI: U3.27(DIN) U11.6(Vo)
ISO_SDO: U3.26(DOUT) U8.2(V1)
ISO_START: R18.1 U2.4(C) U3.23(START)
SSI3CLK: U6.2(V1)
SSI3Fss: U14.2(V1)
SSI3Rx: U8.6(Vo)
SSI3Tx: U11.2(V1)
Vint: C49.2 R24.1 U3.12(AIN1)
Vtherm: C48.1 R23.1 U3.11(AIN0)
NetC1_2: C1.2 U3.9(VREFOUT)
NetC26_1: C26.1 R2.1 U3.1(DVDD)
NetC32_2: C32.2 R3.1 U3.22(AVDD)
NetC33_2: C33.2 R12.1 U3.21(AVSS)
NetJ1_1: J1.1 J4.1
NetJ1_3: J1.3 J4.3
NetJ1_4: J1.4 J4.4
NetJ1_5: J1.5 J4.5
NetJ1_6: J1.6 J4.6
NetJ1_7: J1.7 J4.7
NetJ1_9: J1.9 J4.9
NetJ1_10: J1.10 J4.10
NetJ1_11: J1.11 J4.11
NetJ4_8: J4.8 R15.1
NetJ5_5: J5.5 R43.2
NetJ5_6: J5.6 R23.2
NetJ5_7: J5.7 R24.2
NetJ6_1: J6.1(X) U19.3(IN+)
NetR1_2: R1.2 U1.1(A)
NetR17_2: R17.2 U3.28(SCKLK)
NetR21_1: R21.1 U19.2(IN-) U19.6(OUT)
NetR56_2: R56.2 U2.1(A)
NetR59_2: R59.2 U28.1(A)
NetU3_4: U3.4(~{RESET}) U17.4(~{RESET})

Not connected (* = marked no-connect by the designer): U3 5(REFP0)* 6(REFN0)* 19(IEXC2)* 20(IEXC1)*; U6 3(NC)* 7(NC)*; U8 3(NC) 7(NC); U11 3(NC)* 7(NC)*; U14 3(NC)* 7(NC)*; U29 3(NC) 7(NC)

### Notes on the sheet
- Signal to ADS1248_ISO
- Isolated Circuits
- Isolated ADC
- (near R21) Cl-ISE Reference
- Logic level will be inverted.
- HIGH on MCU = LOW in isolated side
- Source
- (near J4) Counter
- RKO-A
- T1
- Counter
- (near J1) RKO-A
- (near J4) Reference
- RKO-B
- (near J4) Substrate
- Drain
- T3
- (near J1) Reference
- (near J1) RKO-B
- (near J1) Substrate
- (near J1) Drain
- (near J1) T2
- (near U29) Signal from ADS1248_ISO
- T2
- Shield
- (near J1) Shield
- VS-
- VS+
- GND
- pH+

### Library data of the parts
C1 = C1608X5R1A106K080AC: CAP CER 10UF 10V 10% X5R 0603; Manufacturer: TDK Corporation
C26 C30 C32 C33 C35 C39 C46 C48 C49 = C0603C104K5RACTU: as C5 on sheet Cortex Power and Voltage Regulators-E
J1 J4 = 0705430010: CONN HEADER 11POS .100 VERT GOLD; Manufacturer: Molex Inc; Connector Type: Header, Shrouded; Number of Positions: 11; Number of Positions Loaded: All; Pitch: 0.100" (2.54mm)
J5 = 0705430006: as J13 on sheet Cortex Signal-E
J6 = 5226990-1: CONN BNC JACK R/A 50 OHM PCB; Manufacturer: TE Connectivity; Connector Type: Jack, Female Socket; Contact Termination: Solder; Impedance: 50 Ohm; Frequency - Max: 4GHz; Body Material: Zinc; Body Finish: Nickel; Center Contact Material: Phosphor Bronze; Center Contact Plating: Tin; Dielectric Material: Polymethylpentene (PMP)
R1 R56 R59 = ERJ-6GEYJ202V: as R62 on sheet Cortex Signal-E
R2 R3 R12 = ERJ-6GEYJ100V: RES 10 OHM 1/8W 5% 0805 SMD; Manufacturer: Panasonic Electronic Components; Power (Watts): 0.125W, 1/8W; Temperature Coefficient: ±200ppm/°C
R15 R16 R21 R23 R24 = ERJ-6GEYJ103V: as R58 on sheet Cortex Power and Voltage Regulators-E
R17 = ERJ-3GEYJ470V: RES 47 OHM 1/10W 5% 0603 SMD; Manufacturer: Panasonic Electronic Components; Power (Watts): 0.1W, 1/10W; Temperature Coefficient: ±200ppm/°C
R18 R40 R41 = ERJ-6GEYJ104V: as R55 on sheet Cortex Power and Voltage Regulators-E
R43 = ERJ-6ENF2002V: RES 20K OHM 1/8W 1% 0805 SMD; Manufacturer: Panasonic Electronic Components; Power (Watts): 0.125W, 1/8W; Temperature Coefficient: ±100ppm/°C
U1 U2 U28 = FOD8523SD: OPTOCOUPLER DARL 5KVRMS 4SMD; Manufacturer: Fairchild Semiconductor; Number of Channels: 1; Input Type: DC; Voltage - Isolation: 5000Vrms; Current Transfer Ratio (Min): 1000% @ 1mA; Current Transfer Ratio (Max): 15000% @ 1mA; Voltage - Output: 300V; Current - Output / Channel: 150mA; Current - DC Forward (If): 50mA; Vce Saturation (Max): 1.2V; Output Type: Darlington
U3 = ADS1248IPW: IC ADC 24BIT DEL/SIG LN 28TSSOP; Manufacturer: Texas Instruments; Number of Bits: 24; Sampling Rate (Per Second): 2k; Data Interface: Serial, SPI™; Number of Converters: 1; Voltage Supply Source: Analog and Digital, Dual ±; Number of Inputs and Type: 7 Single-Ended, Unipolar; 7 Single-Ended, Bipolar; 4 Differential, Unipolar; 4 Differential, Bipolar
U6 U11 U14 = FOD8001: OPTOCOUPLER 3.3V 8-SOIC; Manufacturer: Fairchild Semiconductor; Voltage - Isolation: 3750Vrms; Number of Channels: 1, Unidirectional; Current - Output / Channel: 10mA; Data Rate: 25Mbps; Propagation Delay High - Low @ If: 25ns; Input Type: Logic; Output Type: Push-Pull, Totem Pole
U8 U29 = FOD8001: OPTOCOUPLER 3.3V 8-SOIC; Manufacturer: Fairchild Semiconductor; Voltage - Isolation: 3750Vrms; Number of Channels: 1, Unidirectional; Current - Output / Channel: 10mA; Input Type: Logic; Output Type: Push-Pull, Totem Pole; Data Rate: 25Mbps; Propagation Delay High - Low @ If: 25ns
U17 = TPS3836L30DBVT: IC 2.64V NANOPWR MON SOT-23-5; Manufacturer: Texas Instruments; Number of Voltages Monitored: 1; Output: Push-Pull, Totem Pole; Reset: Active Low; Reset Timeout: 100 ms Minimum
U19 = LMC6041AIM: IC OPAMP GP 75KHZ RRO 8SOIC; Manufacturer: Texas Instruments; Manufacturer Part Number: LMC6041AIM/NOPB; Amplifier Type: General Purpose; Number of Circuits: 1; Output Type: Rail-to-Rail; Slew Rate: 0.02 V/µs; Current - Input Bias: 0.002pA; Voltage - Input Offset: 1mV; Current - Supply: 18µA; Current - Output / Channel: 40mA; Voltage - Supply, Single/Dual (±): 4.5 V ~ 15.5 V, ±2.25 V ~ 7.75 V

## Sheet RS232 and Perif Sensors-E.SchDoc: SeapHOx ARM Controller
size Letter; DocumentNumber: 1; Revision: E; SheetNumber: 6; SheetTotal: 7
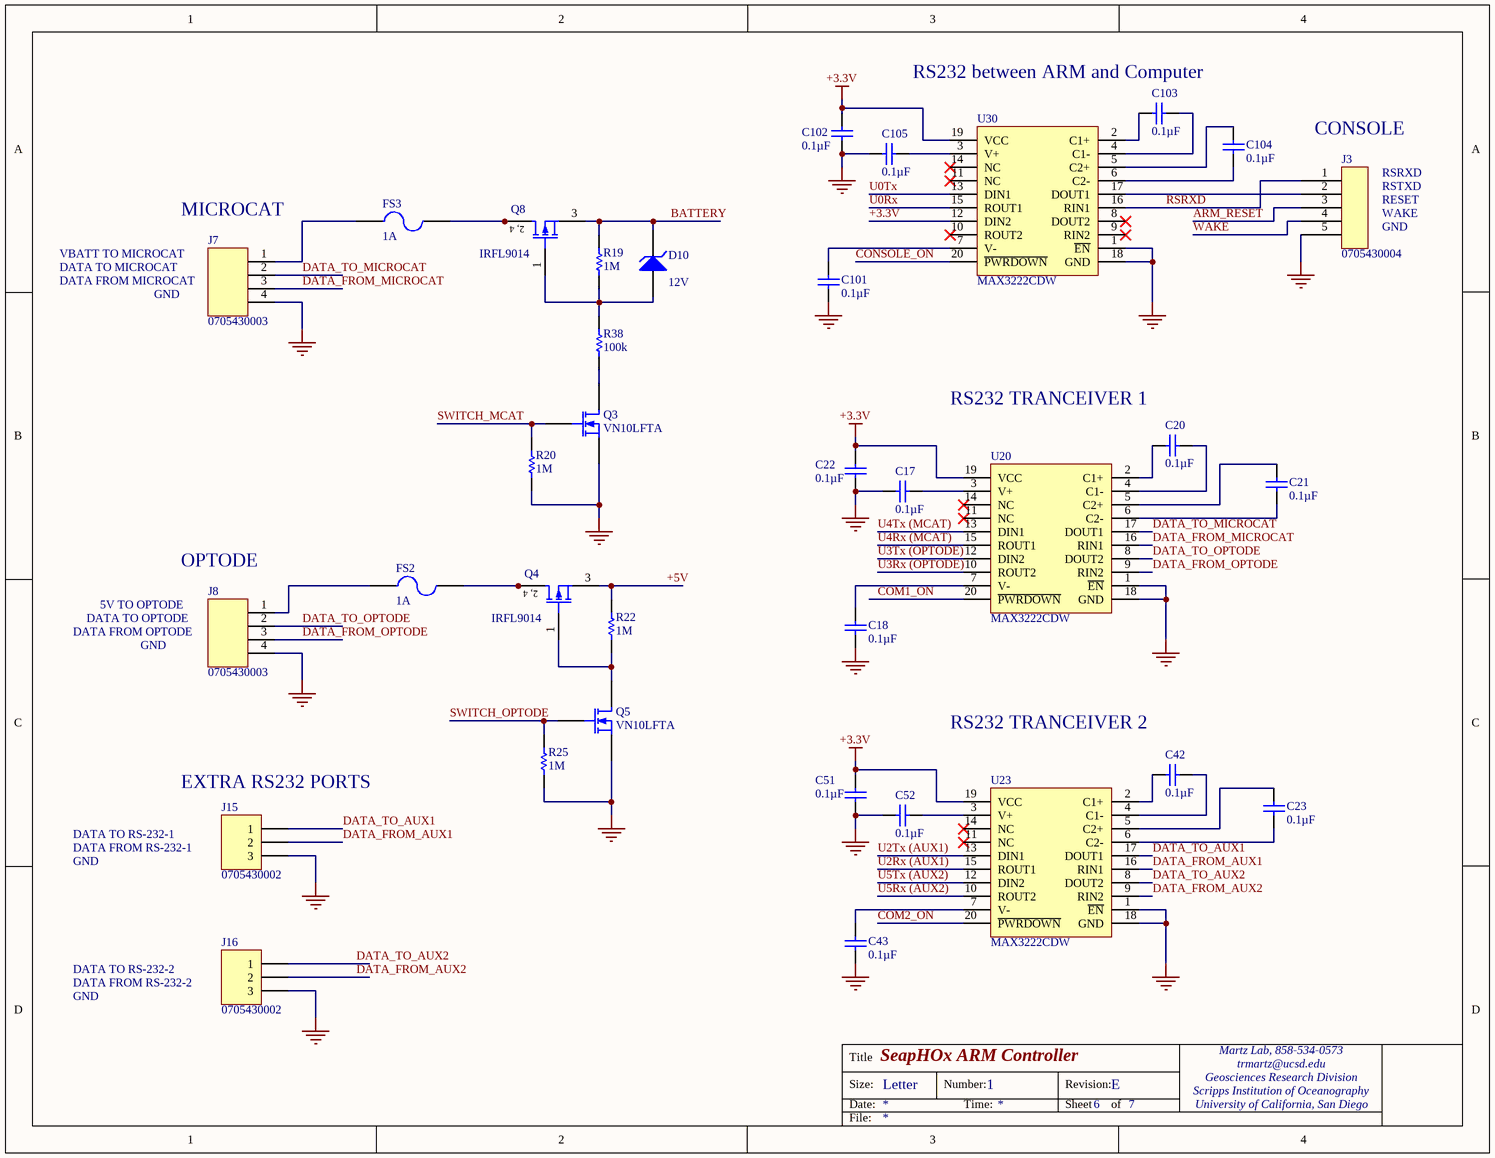
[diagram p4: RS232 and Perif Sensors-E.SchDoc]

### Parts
C17  Capacitance: 0.1µF  [CAPC0603(1608)100_M]  (hidden comment: 0.1uF/50V)
C18  Capacitance: 0.1µF  [CAPC0603(1608)100_M]  (hidden comment: 0.1uF/50V)
C20  Capacitance: 0.1µF  [CAPC0603(1608)100_M]  (hidden comment: 0.1uF/50V)
C21  Capacitance: 0.1µF  [CAPC0603(1608)100_M]  (hidden comment: 0.1uF/50V)
C22  Capacitance: 0.1µF  [CAPC0603(1608)100_M]  (hidden comment: 0.1uF/50V)
C23  Capacitance: 0.1µF  [CAPC0603(1608)100_M]  (hidden comment: 0.1uF/50V)
C42  Capacitance: 0.1µF  [CAPC0603(1608)100_M]  (hidden comment: 0.1uF/50V)
C43  Capacitance: 0.1µF  [CAPC0603(1608)100_M]  (hidden comment: 0.1uF/50V)
C51  Capacitance: 0.1µF  [CAPC0603(1608)100_M]  (hidden comment: 0.1uF/50V)
C52  Capacitance: 0.1µF  [CAPC0603(1608)100_M]  (hidden comment: 0.1uF/50V)
C101  Capacitance: 0.1µF  [CAPC0603(1608)100_M]  (hidden comment: 0.1uF/50V)
C102  Capacitance: 0.1µF  [CAPC0603(1608)100_M]  (hidden comment: 0.1uF/50V)
C103  Capacitance: 0.1µF  [CAPC0603(1608)100_M]  (hidden comment: 0.1uF/50V)
C104  Capacitance: 0.1µF  [CAPC0603(1608)100_M]  (hidden comment: 0.1uF/50V)
C105  Capacitance: 0.1µF  [CAPC0603(1608)100_M]  (hidden comment: 0.1uF/50V)
D10  Voltage - Zener (Nom) (Vz): 12V  [SOD323F 1005]
FS2  Current Rating: 1A  [FUSE-NANO-SMD]  (hidden comment: 5A)
FS3  Current Rating: 1A  [FUSE-NANO-SMD]  (hidden comment: 5A)
J3  0705430004  [70543-0004]
J7  0705430003  [70543-0003]
J8  0705430003  [70543-0003]
J15  0705430002  [70543-0002]
J16  0705430002  [70543-0002]
Q3  VN10LFTA  [SOT23-3]
Q4  IRFL9014  [SOT-223]
Q5  VN10LFTA  [SOT23-3]
Q8  IRFL9014  [SOT-223]
R19  Resistance (Ohms): 1M  [RESC0805(2012)_N]  (hidden comment: ERJ-6GEYJ105V)
R20  Resistance (Ohms): 1M  [RESC0805(2012)_N]  (hidden comment: ERJ-6GEYJ105V)
R22  Resistance (Ohms): 1M  [RESC0805(2012)_N]  (hidden comment: ERJ-6GEYJ105V)
R25  Resistance (Ohms): 1M  [RESC0805(2012)_N]  (hidden comment: ERJ-6GEYJ105V)
R38  Resistance (Ohms): 100k  [RESC0805(2012)_N]  (hidden comment: ERJ-6GEYJ104V)
U20  MAX3222CDW  [SOIC20]
U23  MAX3222CDW  [SOIC20]
U30  MAX3222CDW  [SOIC20]

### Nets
+3.3V: C22.1 C51.1 C102.1 U20.19(VCC) U23.19(VCC) U30.12(DIN2) U30.19(VCC)
+5V: Q4.3(S) R22.2
BATTERY: D10.2(K) Q8.3(S) R19.2
GND: C17.2 C18.2 C22.2 C43.2 C51.2 C52.2 C101.2 C102.2 C105.2 J3.5 J7.4 J8.4 J15.3 J16.3 Q3.2(S) Q5.2(S) R20.1 R25.1 U20.1(~{EN}) U20.18(GND) U23.1(~{EN}) U23.18(GND) U30.1(~{EN}) U30.18(GND)
ARM_RESET: J3.3
COM1_ON: U20.20(~{PWRDOWN})
COM2_ON: U23.20(~{PWRDOWN})
CONSOLE_ON: U30.20(~{PWRDOWN})
DATA_FROM_AUX1: J15.2 U23.16(RIN1)
DATA_FROM_AUX2: J16.2 U23.9(RIN2)
DATA_FROM_MICROCAT: J7.3 U20.16(RIN1)
DATA_FROM_OPTODE: J8.3 U20.9(RIN2)
DATA_TO_AUX1: J15.1 U23.17(DOUT1)
DATA_TO_AUX2: J16.1 U23.8(DOUT2)
DATA_TO_MICROCAT: J7.2 U20.17(DOUT1)
DATA_TO_OPTODE: J8.2 U20.8(DOUT2)
RSRXD: J3.1 U30.16(RIN1)
SWITCH_MCAT: Q3.1(G) R20.2
SWITCH_OPTODE: Q5.1(G) R25.2
U0Rx: U30.15(ROUT1)
U0Tx: U30.13(DIN1)
U2Rx (AUX1): U23.15(ROUT1)
U2Tx (AUX1): U23.13(DIN1)
U3Rx (OPTODE): U20.10(ROUT2)
U3Tx (OPTODE): U20.12(DIN2)
U4Rx (MCAT): U20.15(ROUT1)
U4Tx (MCAT): U20.13(DIN1)
U5Rx (AUX2): U23.10(ROUT2)
U5Tx (AUX2): U23.12(DIN2)
WAKE: J3.4
NetC17_1: C17.1 U20.3(V+)
NetC18_1: C18.1 U20.7(V-)
NetC20_1: C20.1 U20.2(C1+)
NetC20_2: C20.2 U20.4(C1-)
NetC21_1: C21.1 U20.5(C2+)
NetC21_2: C21.2 U20.6(C2-)
NetC23_1: C23.1 U23.5(C2+)
NetC23_2: C23.2 U23.6(C2-)
NetC42_1: C42.1 U23.2(C1+)
NetC42_2: C42.2 U23.4(C1-)
NetC43_1: C43.1 U23.7(V-)
NetC52_1: C52.1 U23.3(V+)
NetC101_1: C101.1 U30.7(V-)
NetC103_1: C103.1 U30.2(C1+)
NetC103_2: C103.2 U30.4(C1-)
NetC104_1: C104.1 U30.5(C2+)
NetC104_2: C104.2 U30.6(C2-)
NetC105_1: C105.1 U30.3(V+)
NetD10_1: D10.1(A) Q8.1(G) R19.1 R38.2
NetFS2_1: FS2.1 J8.1
NetFS2_2: FS2.2 Q4.2(D) Q4.4(D)
NetFS3_1: FS3.1 J7.1
NetFS3_2: FS3.2 Q8.2(D) Q8.4(D)
NetJ3_2: J3.2 U30.17(DOUT1)
NetQ3_3: Q3.3(D) R38.1
NetQ4_1: Q4.1(G) Q5.3(D) R22.1

Not connected (* = marked no-connect by the designer): U20 11(NC)* 14(NC)*; U23 11(NC)* 14(NC)*; U30 8(DOUT2)* 9(RIN2)* 10(ROUT2)* 11(NC)* 14(NC)*

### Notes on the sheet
- (near C103) RS232 between ARM and Computer
- (near J3) CONSOLE
- (near J7) MICROCAT
- (near J3) RSRXD
- (near J3) RSTXD
- (near J3) RESET
- (near J3) WAKE
- (near J3) GND
- DATA TO MICROCAT
- DATA FROM MICROCAT
- VBATT TO MICROCAT
- GND
- RS232 TRANCEIVER 1
- (near J8) OPTODE
- DATA FROM OPTODE
- DATA TO OPTODE
- 5V TO OPTODE
- RS232 TRANCEIVER 2
- DATA TO RS-232-1
- (near J15) EXTRA RS232 PORTS
- DATA FROM RS-232-1
- DATA TO RS-232-2
- DATA FROM RS-232-2

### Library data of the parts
C17 C18 C20-C23 C42 C43 C51 C52 C101-C105 = C0603C104K5RACTU: as C5 on sheet Cortex Power and Voltage Regulators-E
D10 = CZRF52C12: DIODE ZENER 12V 200MW 1005; Manufacturer: Comchip Technology; Voltage - Forward (Vf) (Max) @ If: 900mV @ 10mA; Current - Reverse Leakage @ Vr: 100nA @ 9V; Tolerance: ±5%; Impedance (Max) (Zzt): 20 Ohm
FS2 FS3 = 0157001.DR: FUSE FAST 125VAC, 125VDC 1A SMD; Manufacturer: Littelfuse Inc; Fuse Type: Board Mount (Cartridge Style Excluded); Voltage Rating - AC: 125V; Breaking Capacity @ Rated Voltage: 50A; Melting I²t: 0.459; Approvals: cULus, PSE; DC Cold Resistance: 0.1537 Ohm
J3 = 0705430004: CONN HEADER 5POS .100 VERT GOLD; Manufacturer: Molex Inc; Connector Type: Header, Shrouded; Number of Positions: 5; Number of Positions Loaded: All; Pitch: 0.100" (2.54mm)
J7 J8 = 0705430003: CONN HEADER 4POS .100 VERT GOLD; Manufacturer: Molex Inc; Connector Type: Header, Shrouded; Number of Positions: 4; Number of Positions Loaded: All; Pitch: 0.100" (2.54mm)
J15 J16 = 0705430002: as J23 on sheet Cortex Signal-E
Q3 Q5 = VN10LFTA: MOSFET N-CH 60V 150MA SOT23-3; Manufacturer: Diodes Inc; FET Type: MOSFET N-Channel, Metal Oxide; FET Feature: Standard; Current - Continuous Drain (Id) @ 25° C: 150mA (Ta); Rds On (Max) @ Id, Vgs: 5 Ohm @ 500mA, 10V; Vgs(th) (Max) @ Id: 2.5V @ 1mA; Input Capacitance (Ciss) @ Vds: 60pF @ 25V; Power - Max: 330mW
Q4 Q8 = IRFL9014TRPBF: MOSFET P-CH 60V 1.8A SOT223; Manufacturer: Vishay Siliconix; FET Type: MOSFET P-Channel, Metal Oxide; FET Feature: Standard; Current - Continuous Drain (Id) @ 25° C: 1.8A (Tc); Rds On (Max) @ Id, Vgs: 500 mOhm @ 1.1A, 10V; Vgs(th) (Max) @ Id: 4V @ 250µA; Gate Charge (Qg) @ Vgs: 12nC @ 10V; Input Capacitance (Ciss) @ Vds: 270pF @ 25V; Power - Max: 2W
R19 R20 R22 R25 = ERJ-6GEYJ105V: as R11 on sheet Cortex Power and Voltage Regulators-E
R38 = ERJ-6GEYJ104V: as R55 on sheet Cortex Power and Voltage Regulators-E
U20 U23 U30 = MAX3222CDW: IC DRVR/RCVR MULTCH RS232 20SOIC; Manufacturer: Texas Instruments; Number of Drivers/Receivers: 2/2; Duplex: Full; Receiver Hysteresis: 300mV; Data Rate: 250kbps; Voltage - Supply: 3 V ~ 5.5 V

## Sheet Isolated Power Circuits-E.SchDoc: SeapHOx ARM Controller
size Letter; DocumentNumber: 1; Revision: E; SheetNumber: 2; SheetTotal: 7; PageSetup: Record=PageOptions¦CenterHorizontal=True¦CenterVertical=True¦PrintScale=0.94¦XCorrection=1.00¦YCorrection=1.00¦PrintKind=0¦BorderSize=5000000¦LeftOffset=0¦BottomOffset=0¦Orientation=2¦PaperLength=1000¦PaperWidth=1000¦Scale=100¦PaperSource=7¦PrintQuality=-4¦MediaType=1¦DitherType=10¦PaperKind=Letter¦PrintScaleMode=1
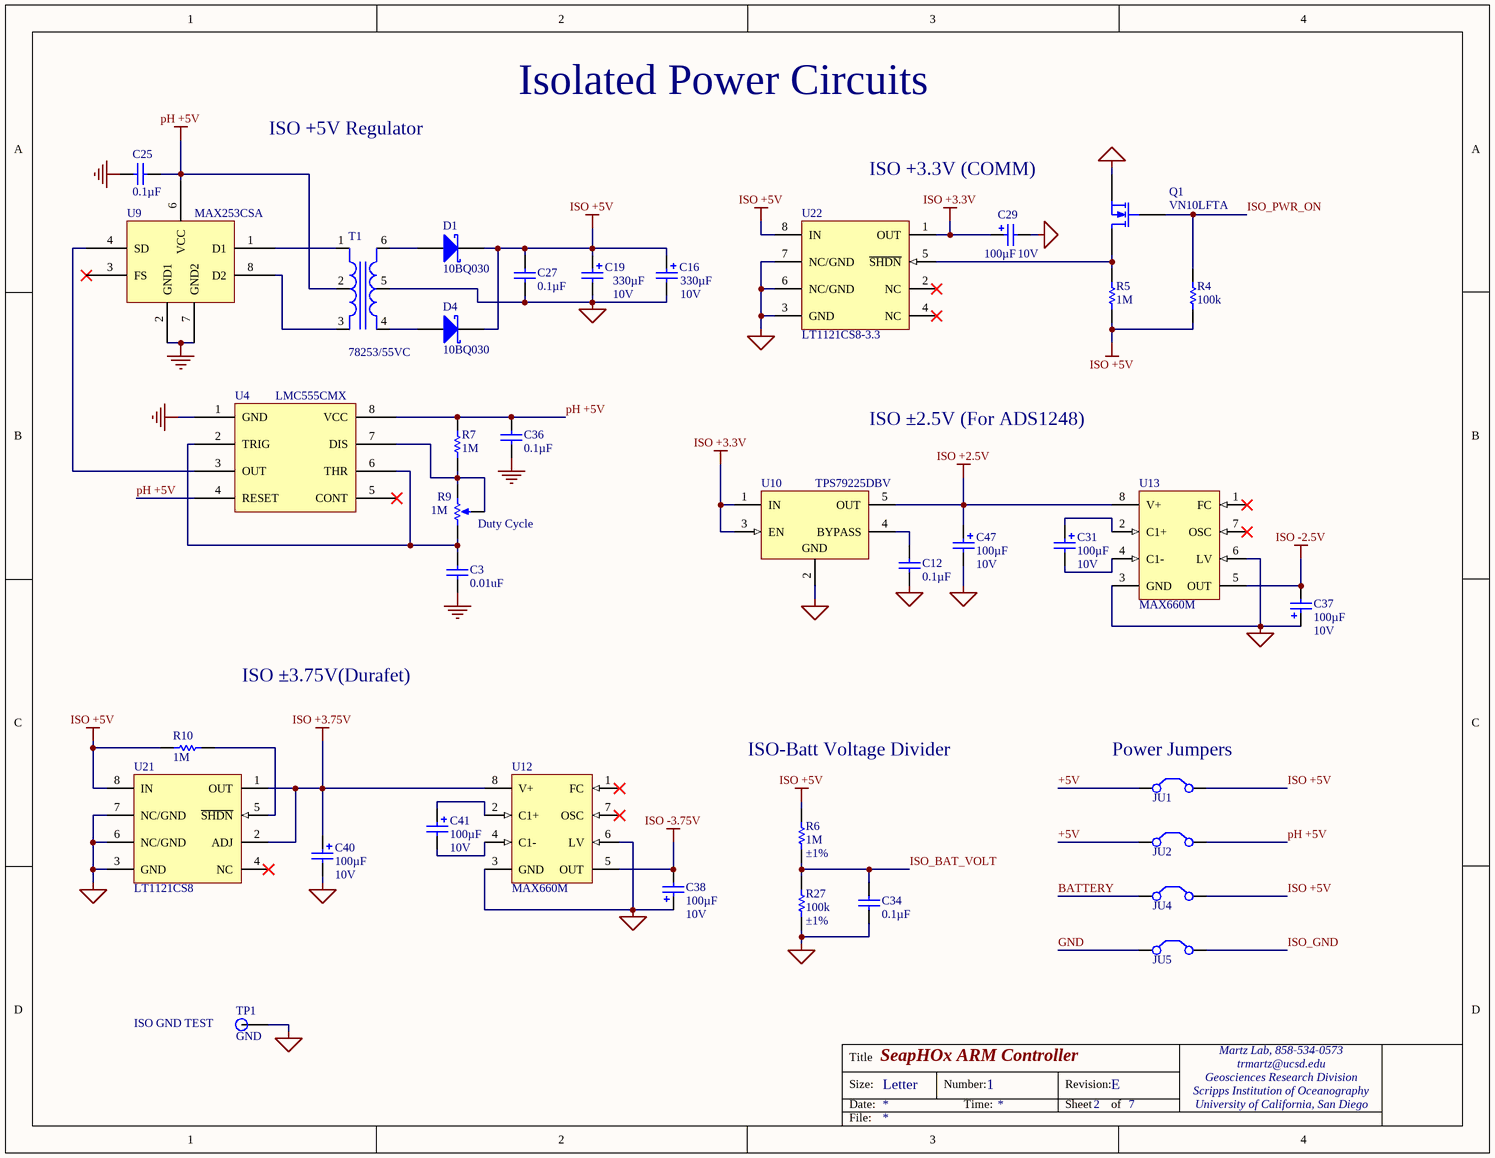
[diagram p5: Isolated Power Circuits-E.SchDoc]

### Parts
C3  0.01uF  [CAPC0603(1608)100_M]
C12  Capacitance: 0.1µF  [CAPC0603(1608)100_M]  (hidden comment: 0.1uF/50V)
C16  Voltage - Rated: 10V  Capacitance: 330µF  [CAPMP7343X29N]  (hidden comment: TR3D337M010C0100)
C19  Voltage - Rated: 10V  Capacitance: 330µF  [CAPMP7343X29N]  (hidden comment: TR3D337M010C0100)
C25  Capacitance: 0.1µF  [CAPC0603(1608)100_M]  (hidden comment: 0.1uF/50V)
C27  Capacitance: 0.1µF  [CAPC0603(1608)100_M]  (hidden comment: 0.1uF/50V)
C29  Capacitance: 100µF  Voltage - Rated: 10V  [CAPMP7343X29N]  (hidden comment: T495D107K010ATE100)
C31  Capacitance: 100µF  Voltage - Rated: 10V  [CAPMP7343X29N]  (hidden comment: T495D107K010ATE100)
C34  Capacitance: 0.1µF  [CAPC0603(1608)100_M]  (hidden comment: 0.1uF/50V)
C36  Capacitance: 0.1µF  [CAPC0603(1608)100_M]  (hidden comment: 0.1uF/50V)
C37  Capacitance: 100µF  Voltage - Rated: 10V  [CAPMP7343X29N]  (hidden comment: T495D107K010ATE100)
C38  Capacitance: 100µF  Voltage - Rated: 10V  [CAPMP7343X29N]  (hidden comment: T495D107K010ATE100)
C40  Capacitance: 100µF  Voltage - Rated: 10V  [CAPMP7343X29N]  (hidden comment: T495D107K010ATE100)
C41  Capacitance: 100µF  Voltage - Rated: 10V  [CAPMP7343X29N]  (hidden comment: T495D107K010ATE100)
C47  Capacitance: 100µF  Voltage - Rated: 10V  [CAPMP7343X29N]  (hidden comment: T495D107K010ATE100)
D1  10BQ030  [DO214AA]
D4  10BQ030  [DO214AA]
JU1  68001-202HLF  [Jump-2 100mil]  (value not drawn)
JU2  68001-202HLF  [Jump-2 100mil]  (value not drawn)
JU4  68001-202HLF  [Jump-2 100mil]  (value not drawn)
JU5  68001-202HLF  [Jump-2 100mil]  (value not drawn)
Q1  VN10LFTA  [SOT23-3]
R4  Resistance (Ohms): 100k  [RESC0805(2012)_N]  (hidden comment: ERJ-6GEYJ104V)
R5  Resistance (Ohms): 1M  [RESC0805(2012)_N]  (hidden comment: ERJ-6GEYJ105V)
R6  Resistance (Ohms): 1M  Tolerance: ±1%  [RESC0805(2012)_N]  (hidden comment: ERJ-6ENF1004V)
R7  Resistance (Ohms): 1M  [RESC0805(2012)_N]  (hidden comment: ERJ-6GEYJ105V)
R9  Resistance (Ohms): 1M  [3269W]  (hidden comment: 3269W-1-105GLF)
R10  Resistance (Ohms): 1M  [RESC0805(2012)_N]  (hidden comment: ERJ-6GEYJ105V)
R27  Resistance (Ohms): 100k  Tolerance: ±1%  [RESC0805(2012)_N]  (hidden comment: ERJ-6ENF1003V)
T1  78253/55VC  [DIP6]
TP1  GND  [TEST-POINT-0.063]
U4  LMC555CMX  [MS-012-AA]
U9  MAX253CSA  [SOIC8]
U10  TPS79225DBV  [TI-DBV5]
U12  MAX660M  [SOIC8]
U13  MAX660M  [SOIC8]
U21  LT1121CS8  [SOIC8]
U22  LT1121CS8-3.3  [SOIC8]

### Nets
+5V: JU1.1(C1) JU2.1(C1)
BATTERY: JU4.1(C1)
GND: C3.2 C25.2 C36.1 JU5.1(C1) U4.1(GND) U9.2(GND1) U9.7(GND2)
ISO +2.5V: C47.1 U10.5(OUT) U13.8(V+)
ISO +3.3V: C29.1 U10.1(IN) U10.3(EN) U22.1(OUT)
ISO +3.75V: C40.1 U12.8(V+) U21.1(OUT) U21.2(ADJ)
ISO +5V: C16.1 C19.1 C27.2 D1.2(K) D4.2(K) JU1.2(C2) JU4.2(C2) R4.1 R5.1 R6.2 R10.2 U21.8(IN) U22.8(IN)
ISO -2.5V: C37.2 U13.5(OUT)
ISO -3.75V: C38.2 U12.5(OUT)
ISO_GND: C12.1 C16.2 C19.2 C27.1 C29.2 C34.1 C37.1 C38.1 C40.2 C47.2 JU5.2(C2) Q1.2(S) R27.1 T1.5(SCT) TP1.1(TP) U10.2(GND) U12.3(GND) U12.6(LV) U13.3(GND) U13.6(LV) U21.3(GND) U21.6(NC/GND) U21.7(NC/GND) U22.3(GND) U22.6(NC/GND) U22.7(NC/GND)
pH +5V: C25.1 C36.2 JU2.2(C2) R7.2 T1.2(PCT) U4.4(RESET) U4.8(VCC) U9.6(VCC)
ISO_BAT_VOLT: C34.2 R6.1 R27.2
ISO_PWR_ON: Q1.1(G) R4.2
NetC3_1: C3.1 R9.3(CW) U4.2(TRIG) U4.6(THR)
NetC12_2: C12.2 U10.4(BYPASS)
NetC31_1: C31.1 U13.2(C1+)
NetC31_2: C31.2 U13.4(C1-)
NetC41_1: C41.1 U12.2(C1+)
NetC41_2: C41.2 U12.4(C1-)
NetD1_1: D1.1(A) T1.6(S1)
NetD4_1: D4.1(A) T1.4(S2)
NetQ1_3: Q1.3(D) R5.2 U22.5(~{SHDN})
NetR7_1: R7.1 R9.1(CCW) R9.2(W) U4.7(DIS)
NetR10_1: R10.1 U21.5(~{SHDN})
NetT1_1: T1.1(P1) U9.1(D1)
NetT1_3: T1.3(P2) U9.8(D2)
NetU4_3: U4.3(OUT) U9.4(SD)

Not connected (* = marked no-connect by the designer): U4 5(CONT)*; U9 3(FS)*; U12 1(FC)* 7(OSC)*; U13 1(FC)* 7(OSC)*; U21 4(NC)*; U22 2(NC)* 4(NC)*

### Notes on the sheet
- Isolated Power Circuits
- ISO +5V Regulator
- ISO +3.3V (COMM)
- ISO ±2.5V (For ADS1248)
- (near R9) Duty Cycle
- ISO ±3.75V(Durafet)
- ISO-Batt Voltage Divider
- (near JU1) Power Jumpers
- (near TP1) ISO GND TEST

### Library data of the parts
C3 = C1608X7R1H103K080AA: as C8 on sheet Cortex Power and Voltage Regulators-E
C12 C25 C27 C34 C36 = C0603C104K5RACTU: as C5 on sheet Cortex Power and Voltage Regulators-E
C16 C19 = TR3D337M010C0100: CAP TANT 330UF 10V 20% 2917; Manufacturer: Vishay Sprague; Manufacturer Size Code: D; ESR (Equivalent Series Resistance): 100 mOhm; Type: Molded
C29 C31 C37 C38 C40 C41 C47 = T495D107K010ATE100: as C6 on sheet Cortex Power and Voltage Regulators-E
D1 D4 = VS-10BQ030TRPBF: DIODE SCHOTTKY 30V 1A DO214AA; Manufacturer: Vishay Semiconductor Diodes Division; Voltage - Forward (Vf) (Max) @ If: 420mV @ 1A; Speed: Fast Recovery =< 500ns, > 200mA (Io); Current - Reverse Leakage @ Vr: 500µA @ 30V; Thermal Resistance: 25°C/W Jl
JU1 JU2 JU4 JU5 = 68001-202HLF: as JU7 on sheet Cortex Signal-E
Q1 = VN10LFTA: as Q3 on sheet RS232 and Perif Sensors-E
R4 = ERJ-6GEYJ104V: as R55 on sheet Cortex Power and Voltage Regulators-E
R5 R7 R10 = ERJ-6GEYJ105V: as R11 on sheet Cortex Power and Voltage Regulators-E
R6 = ERJ-6ENF1004V: RES 1M OHM 1/8W 1% 0805 SMD; Manufacturer: Panasonic Electronic Components; Power (Watts): 0.125W, 1/8W; Temperature Coefficient: ±100ppm/°C
R9 = 3269W-1-105GLF: TRIMMER 1M OHM 0.25W SMD; Manufacturer: Bourns Inc.; Power (Watts): 0.25W, 1/4W; Temperature Coefficient: ±100ppm/°C; Tolerance: ±10%; Number of Turns: 12; Adjustment Type: Top Adjustment; Resistive Material: Cermet
R27 = ERJ-6ENF1003V: RES 100K OHM 1/8W 1% 0805 SMD; Manufacturer: Panasonic Electronic Components; Power (Watts): 0.125W, 1/8W; Temperature Coefficient: ±100ppm/°C
T1 = 78253/55VC: XFRMR 5V IN/OUT MAX 253 DIP; Manufacturer: Murata Power Solutions Inc; Inductance: 240µH; For Use With/Related Products: MAX253
TP1 = 5006: as TP2 on sheet Cortex Power and Voltage Regulators-E
U4 = LMC555CMX: IC OSC MONO TIMING 3MHZ 8-SOIC; Manufacturer: Texas Instruments; Voltage - Supply: 1.5 V ~ 15 V; Current - Supply: 150µA
U9 = MAX253CSA: Gate Drivers Transformer Driver for Iso RS-485 Int; Manufacturer: Maxim Integrated; Manufacturer Part Number: MAX253CSA+; Output Current: 1 A; Supply Current: 0.45 mA; Maximum Power Dissipation: 471 mW; Number of Drivers: 1; Operating Supply Voltage: 3.3 V, 5 V; Supply Voltage - Max: 6 V; Supply Voltage - Min: 2.5 V
U10 = TPS79225DBVT: as U24 on sheet Cortex Power and Voltage Regulators-E
U12 U13 = MAX660M: as U18 on sheet Cortex Power and Voltage Regulators-E
U21 = LT1121CS8: IC REG LDO ADJ 0.15A 8SOIC; Manufacturer: Linear Technology; Manufacturer Part Number: LT1121CS8#PBF; Number of Regulators: 1; Regulator Topology: Positive Adjustable; Voltage - Input: 4.17 V ~ 30 V; Voltage - Output: 3.75 V ~ 30 V; Voltage - Dropout (Typical): 0.42V @ 150mA; Current - Output: 150mA
U22 = LT1121CS8-3.3: as U25 on sheet Cortex Power and Voltage Regulators-E

## Sheet Main Non-Isolated ADC-E.SchDoc: SeapHOx ARM Controller
size Letter; DocumentNumber: 1; Revision: E; SheetNumber: 5; SheetTotal: 7
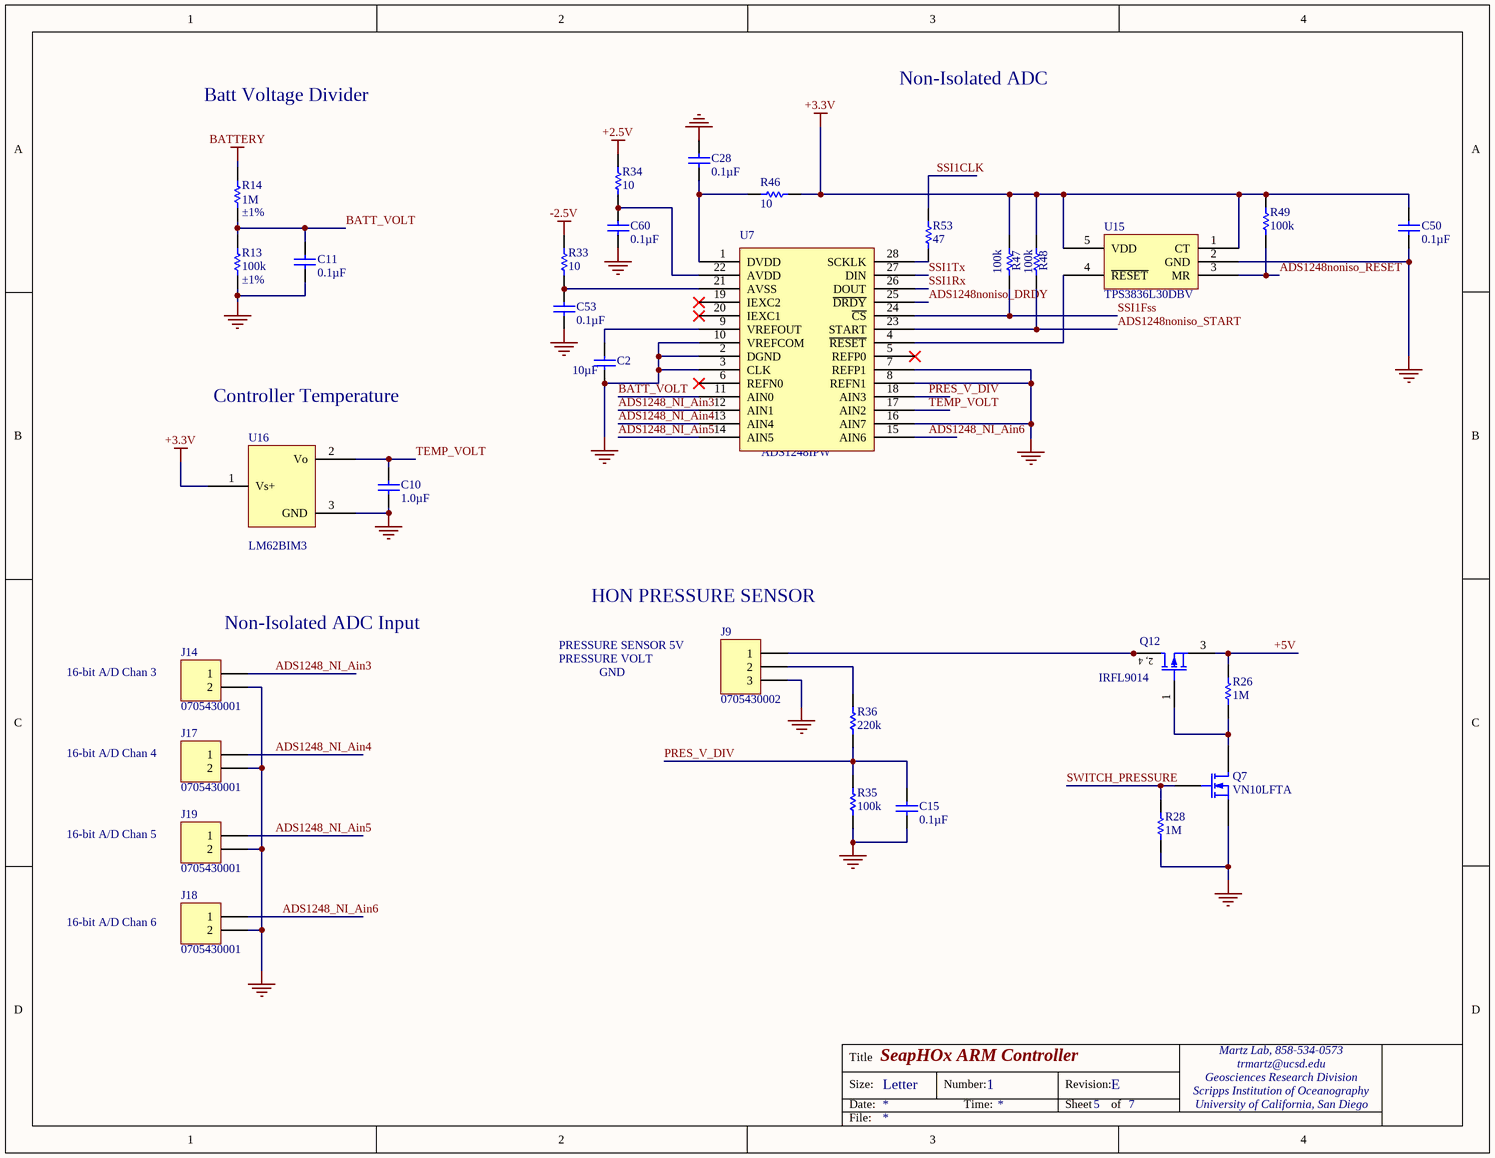
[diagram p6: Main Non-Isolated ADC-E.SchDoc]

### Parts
C2  Capacitance: 10µF  [CAPC0603(1608)100_M]  (hidden comment: C1608X5R1A106K080AC)
C10  Capacitance: 1.0µF  [CAPC0603(1608)100_M]  (hidden comment: C1608X5R1H105K080AB)
C11  Capacitance: 0.1µF  [CAPC0603(1608)100_M]  (hidden comment: 0.1uF/50V)
C15  Capacitance: 0.1µF  [CAPC0603(1608)100_M]  (hidden comment: 0.1uF/50V)
C28  Capacitance: 0.1µF  [CAPC0603(1608)100_M]  (hidden comment: 0.1uF/50V)
C50  Capacitance: 0.1µF  [CAPC0603(1608)100_M]  (hidden comment: 0.1uF/50V)
C53  Capacitance: 0.1µF  [CAPC0603(1608)100_M]  (hidden comment: 0.1uF/50V)
C60  Capacitance: 0.1µF  [CAPC0603(1608)100_M]  (hidden comment: 0.1uF/50V)
J9  0705430002  [70543-0002]
J14  0705430001  [70543-0001]
J17  0705430001  [70543-0001]
J18  0705430001  [70543-0001]
J19  0705430001  [70543-0001]
Q7  VN10LFTA  [SOT23-3]
Q12  IRFL9014  [SOT-223]
R13  Resistance (Ohms): 100k  Tolerance: ±1%  [RESC0805(2012)_N]  (hidden comment: ERJ-6ENF1003V)
R14  Resistance (Ohms): 1M  Tolerance: ±1%  [RESC0805(2012)_N]  (hidden comment: 1.00M/1%)
R26  Resistance (Ohms): 1M  [RESC0805(2012)_N]  (hidden comment: ERJ-6GEYJ105V)
R28  Resistance (Ohms): 1M  [RESC0805(2012)_N]  (hidden comment: ERJ-6GEYJ105V)
R33  Resistance (Ohms): 10  [RESC0805(2012)_N]  (hidden comment: ERJ-6GEYJ100V)
R34  Resistance (Ohms): 10  [RESC0805(2012)_N]  (hidden comment: ERJ-6GEYJ100V)
R35  Resistance (Ohms): 100k  [RESC0805(2012)_N]  (hidden comment: ERJ-6GEYJ104V)
R36  Resistance (Ohms): 220k  [RESC0805(2012)_N]  (hidden comment: ERJ-6GEYJ224V)
R46  Resistance (Ohms): 10  [RESC0805(2012)_N]  (hidden comment: ERJ-6GEYJ100V)
R47  Resistance (Ohms): 100k  [RESC0805(2012)_N]  (hidden comment: ERJ-6GEYJ104V)
R48  Resistance (Ohms): 100k  [RESC0805(2012)_N]  (hidden comment: ERJ-6GEYJ104V)
R49  Resistance (Ohms): 100k  [RESC0805(2012)_N]  (hidden comment: ERJ-6GEYJ104V)
R53  Resistance (Ohms): 47  [RESC0603(1608)_N]  (hidden comment: ERJ-3GEYJ470V)
U7  ADS1248  [TSSOP28]  (value not drawn)
U15  TPS3836L30DBV  [SOT23-5]
U16  LM62BIM3  [SOT23-3]

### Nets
+2.5V: R34.2
+3.3V: C50.2 R46.2 R47.2 R48.2 R49.2 U15.1(CT) U15.5(VDD) U16.1(Vs+)
+5V: Q12.3(S) R26.2
-2.5V: R33.2
BATTERY: R14.2
GND: C2.1 C10.2 C11.1 C15.1 C28.2 C50.1 C53.1 C60.1 J9.3 J14.2 J17.2 J18.2 J19.2 Q7.2(S) R13.1 R28.1 R35.2 U7.2(DGND) U7.3(CLK) U7.7(REFP1) U7.8(REFN1) U7.10(VREFCOM) U7.16(AIN7) U15.2(GND) U16.3(GND)
ADS1248_NI_Ain3: J14.1 U7.12(AIN1)
ADS1248_NI_Ain4: J17.1 U7.13(AIN4)
ADS1248_NI_Ain5: J19.1 U7.14(AIN5)
ADS1248_NI_Ain6: J18.1 U7.15(AIN6)
ADS1248noniso_DRDY: U7.25(~{DRDY})
ADS1248noniso_RESET: R49.1 U15.3(MR)
ADS1248noniso_START: R48.1 U7.23(START)
BATT_VOLT: C11.2 R13.2 R14.1 U7.11(AIN0)
PRES_V_DIV: C15.2 R35.1 R36.2 U7.18(AIN3)
SSI1CLK: R53.1
SSI1Fss: R47.1 U7.24(~{CS})
SSI1Rx: U7.26(DOUT)
SSI1Tx: U7.27(DIN)
SWITCH_PRESSURE: Q7.1(G) R28.2
TEMP_VOLT: C10.1 U7.17(AIN2) U16.2(Vo)
NetC2_2: C2.2 U7.9(VREFOUT)
NetC28_1: C28.1 R46.1 U7.1(DVDD)
NetC53_2: C53.2 R33.1 U7.21(AVSS)
NetC60_2: C60.2 R34.1 U7.22(AVDD)
NetJ9_1: J9.1 Q12.2(D) Q12.4(D)
NetJ9_2: J9.2 R36.1
NetQ7_3: Q7.3(D) Q12.1(G) R26.1
NetR53_2: R53.2 U7.28(SCKLK)
NetU7_4: U7.4(~{RESET}) U15.4(~{RESET})

Not connected (* = marked no-connect by the designer): U7 5(REFP0)* 6(REFN0)* 19(IEXC2)* 20(IEXC1)*

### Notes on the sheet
- Batt Voltage Divider
- Non-Isolated ADC
- Controller Temperature
- (near J14) Non-Isolated ADC Input
- (near J9) HON PRESSURE SENSOR
- (near J14) 16-bit A/D Chan 3
- PRESSURE SENSOR 5V
- PRESSURE VOLT
- GND
- 16-bit A/D Chan 4
- 16-bit A/D Chan 5
- (near J18) 16-bit A/D Chan 6

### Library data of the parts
C2 = C1608X5R1A106K080AC: as C1 on sheet Isolated Circuits-E
C10 = C1608X5R1H105K080AB: as C9 on sheet Cortex Power and Voltage Regulators-E
C11 C15 C28 C50 C53 C60 = C0603C104K5RACTU: as C5 on sheet Cortex Power and Voltage Regulators-E
J9 = 0705430002: as J23 on sheet Cortex Signal-E
J14 J17-J19 = 0705430001: as J21 on sheet Cortex Power and Voltage Regulators-E
Q7 = VN10LFTA: as Q3 on sheet RS232 and Perif Sensors-E
Q12 = IRFL9014TRPBF: as Q4 on sheet RS232 and Perif Sensors-E
R13 = ERJ-6ENF1003V: as R27 on sheet Isolated Power Circuits-E
R14 = ERJ-6ENF1004V: RES 1.00M OHM 1/8W 1% 0805 SMD; Manufacturer: Panasonic Electronic Components; Power (Watts): 0.125W, 1/8W; Temperature Coefficient: ±100ppm/°C
R26 R28 = ERJ-6GEYJ105V: as R11 on sheet Cortex Power and Voltage Regulators-E
R33 R34 R46 = ERJ-6GEYJ100V: as R2 on sheet Isolated Circuits-E
R35 R47-R49 = ERJ-6GEYJ104V: as R55 on sheet Cortex Power and Voltage Regulators-E
R36 = ERJ-6GEYJ224V: as R57 on sheet Cortex Power and Voltage Regulators-E
R53 = ERJ-3GEYJ470V: as R17 on sheet Isolated Circuits-E
U7 = ADS1248IPW: as U3 on sheet Isolated Circuits-E
U15 = TPS3836L30DBVT: as U17 on sheet Isolated Circuits-E
U16 = LM62BIM3: IC TEMP SENSOR 2.7V SOT23-3; Manufacturer: Texas Instruments; Sensing Temperature: 0°C ~ 90°C; Output Type: Voltage; Voltage - Supply: 2.7 V ~ 10 V; Accuracy: ±2°C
